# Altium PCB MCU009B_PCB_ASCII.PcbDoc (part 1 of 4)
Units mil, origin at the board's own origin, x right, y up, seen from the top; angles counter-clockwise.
Board outline 2657.23 x 2215.46 mil, 10 copper layers (Top Layer, Internal-Plane 2, Mid-Layer 3, Mid-Layer 4, Internal-Plane 5, Internal-Plane 6, Mid-Layer 7, Mid-Layer 8, Internal-Plane 9, Bottom Layer), stack 60.8 mil thick; 232 components, 196 nets, 851 pads, 493 vias.
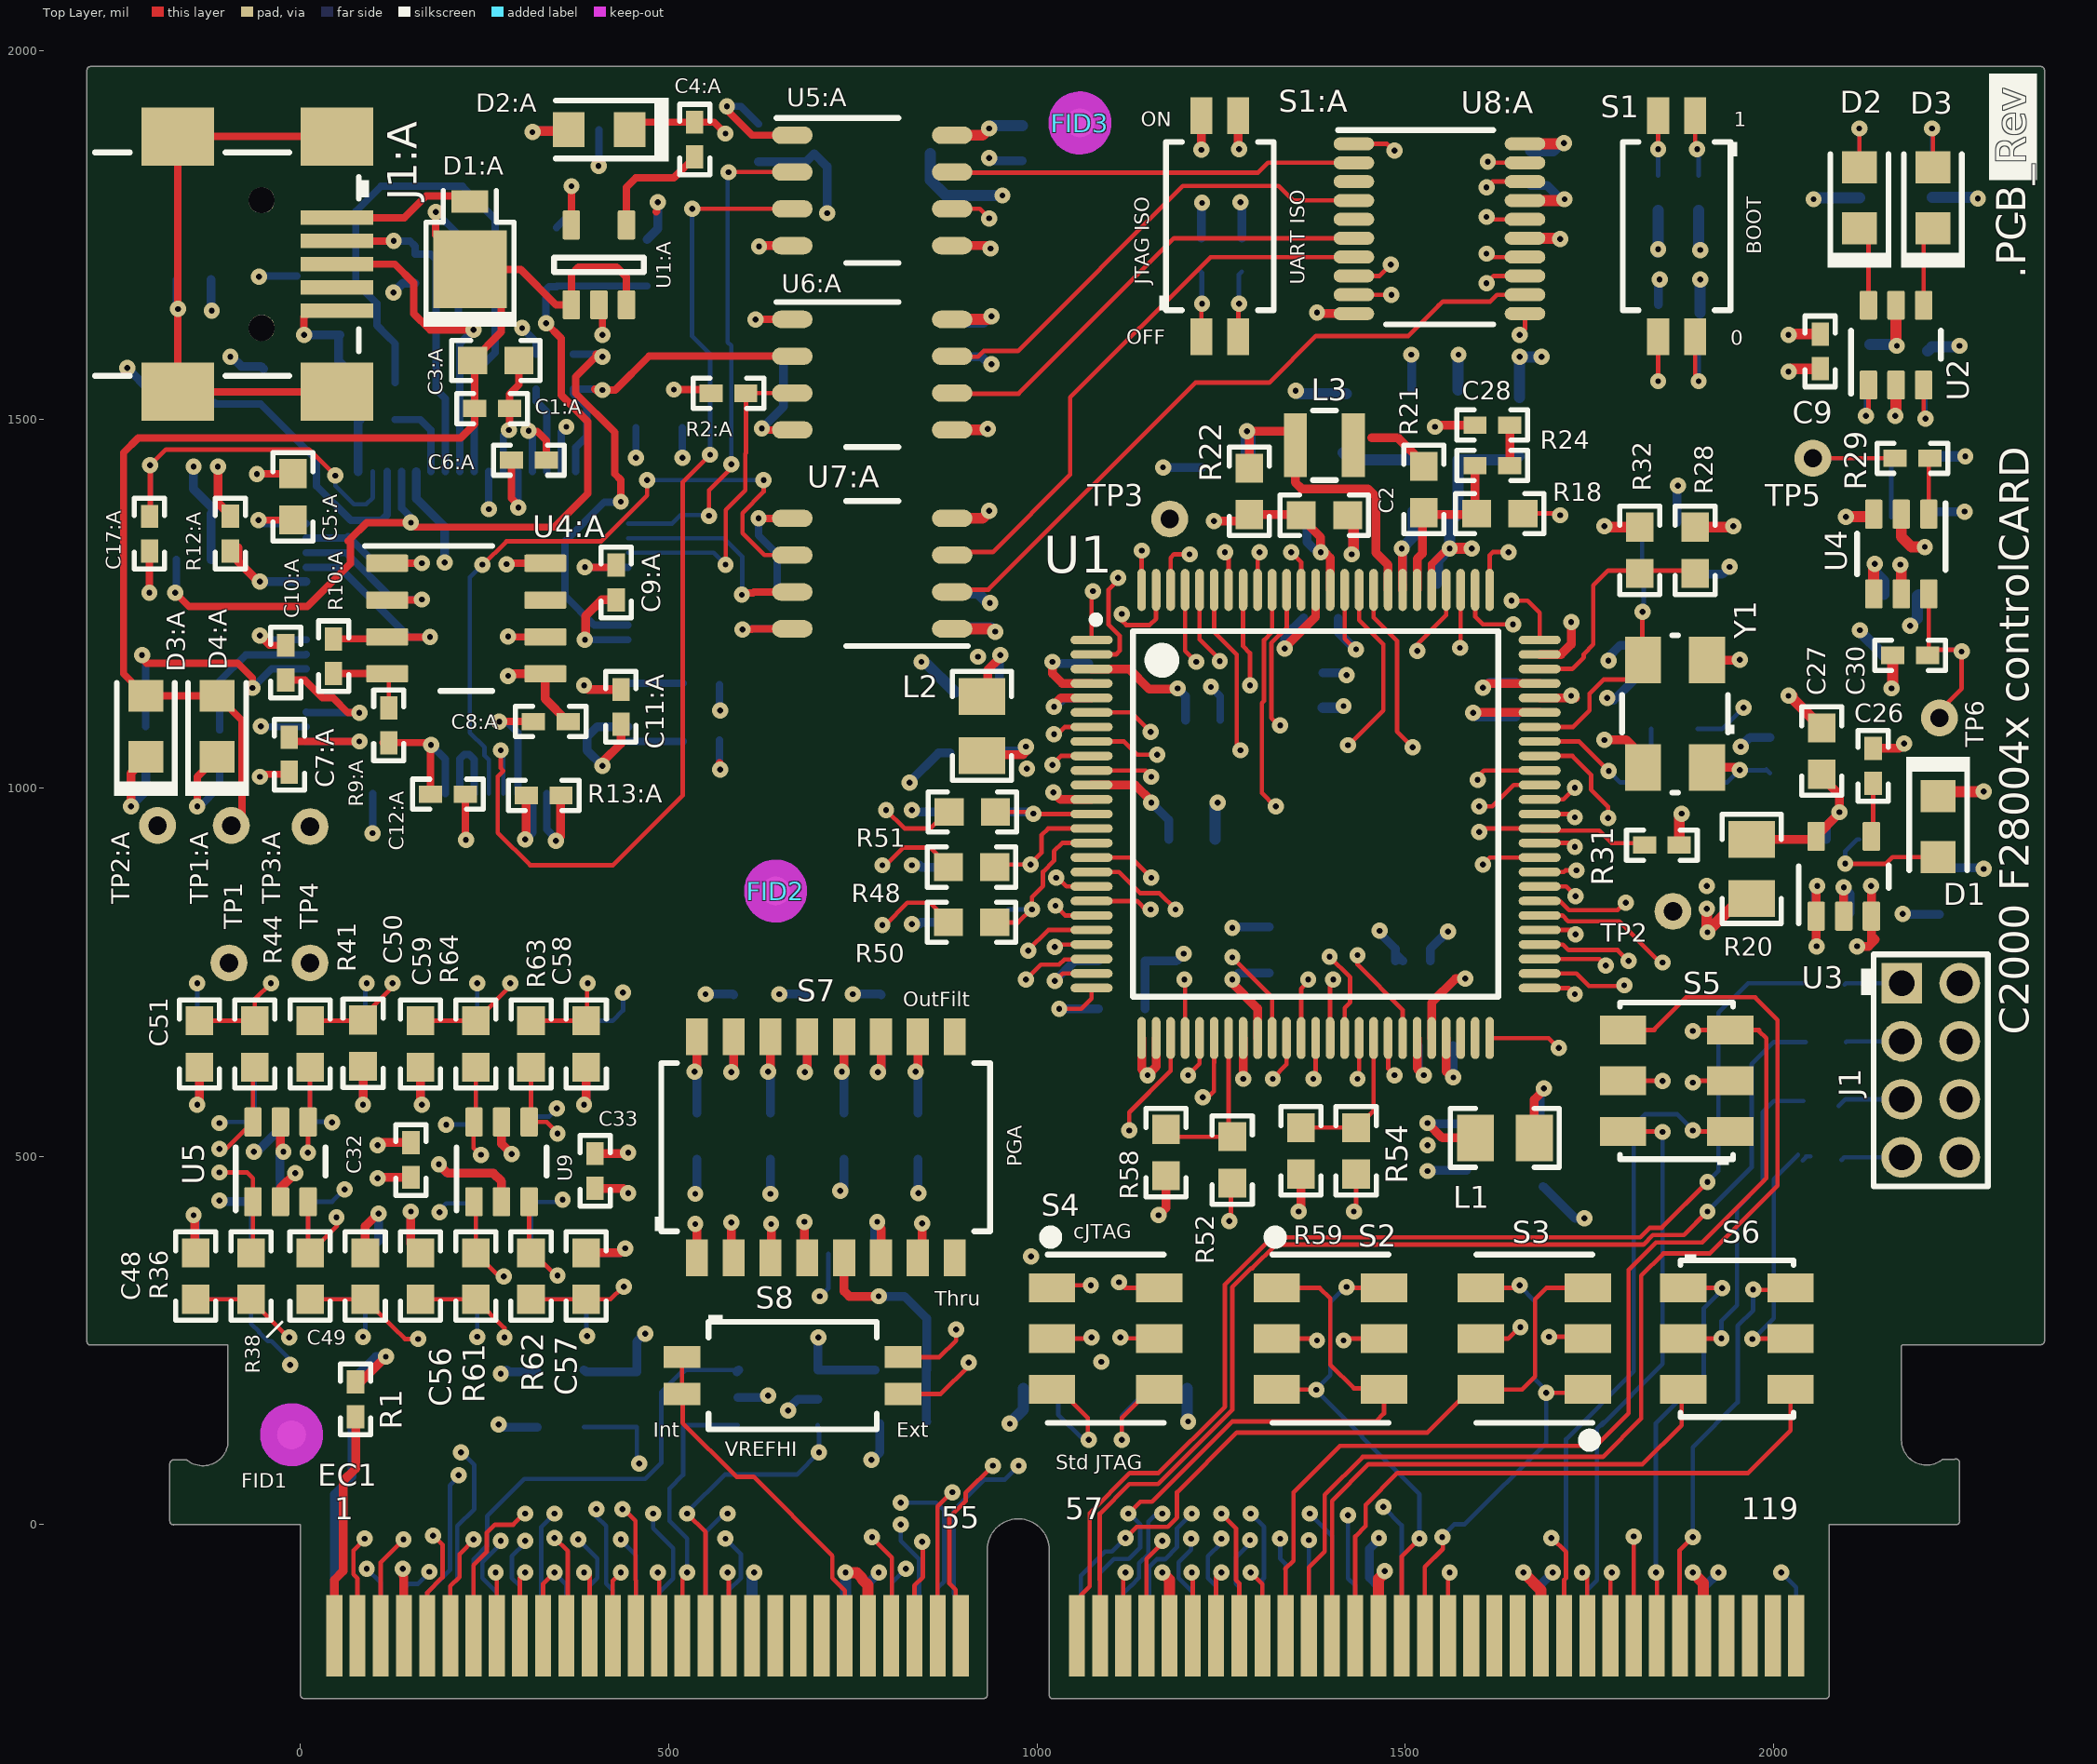
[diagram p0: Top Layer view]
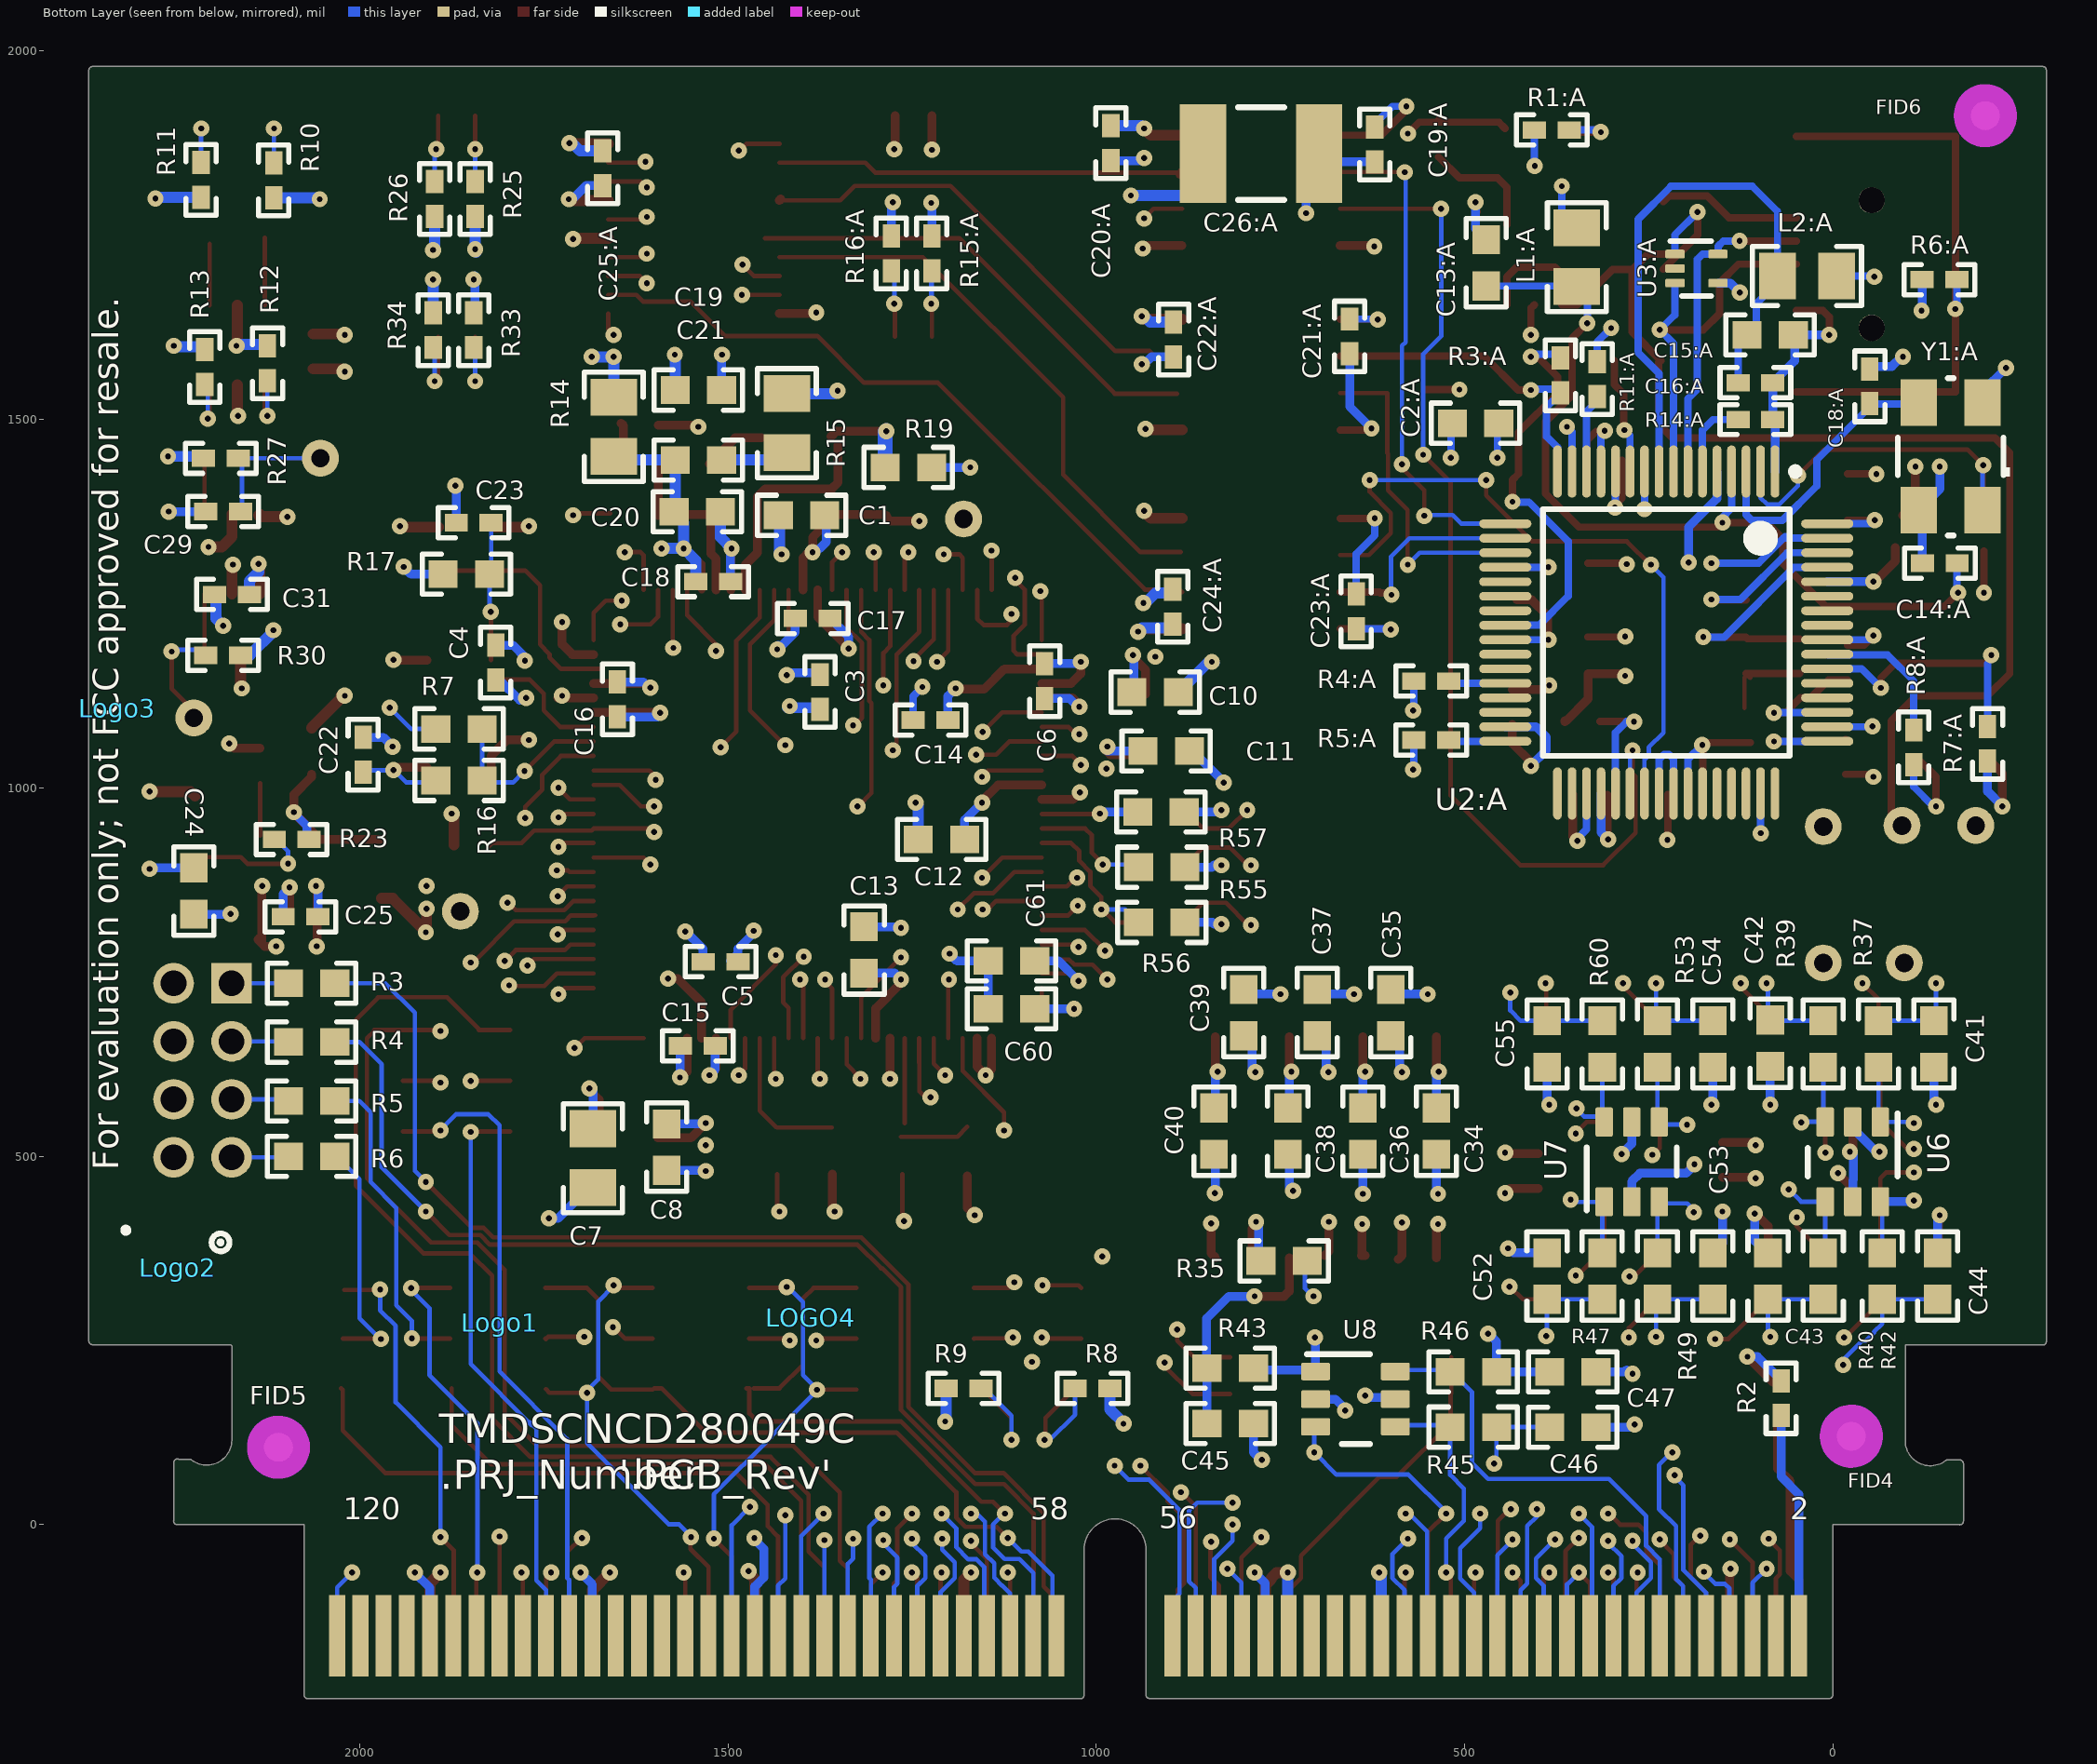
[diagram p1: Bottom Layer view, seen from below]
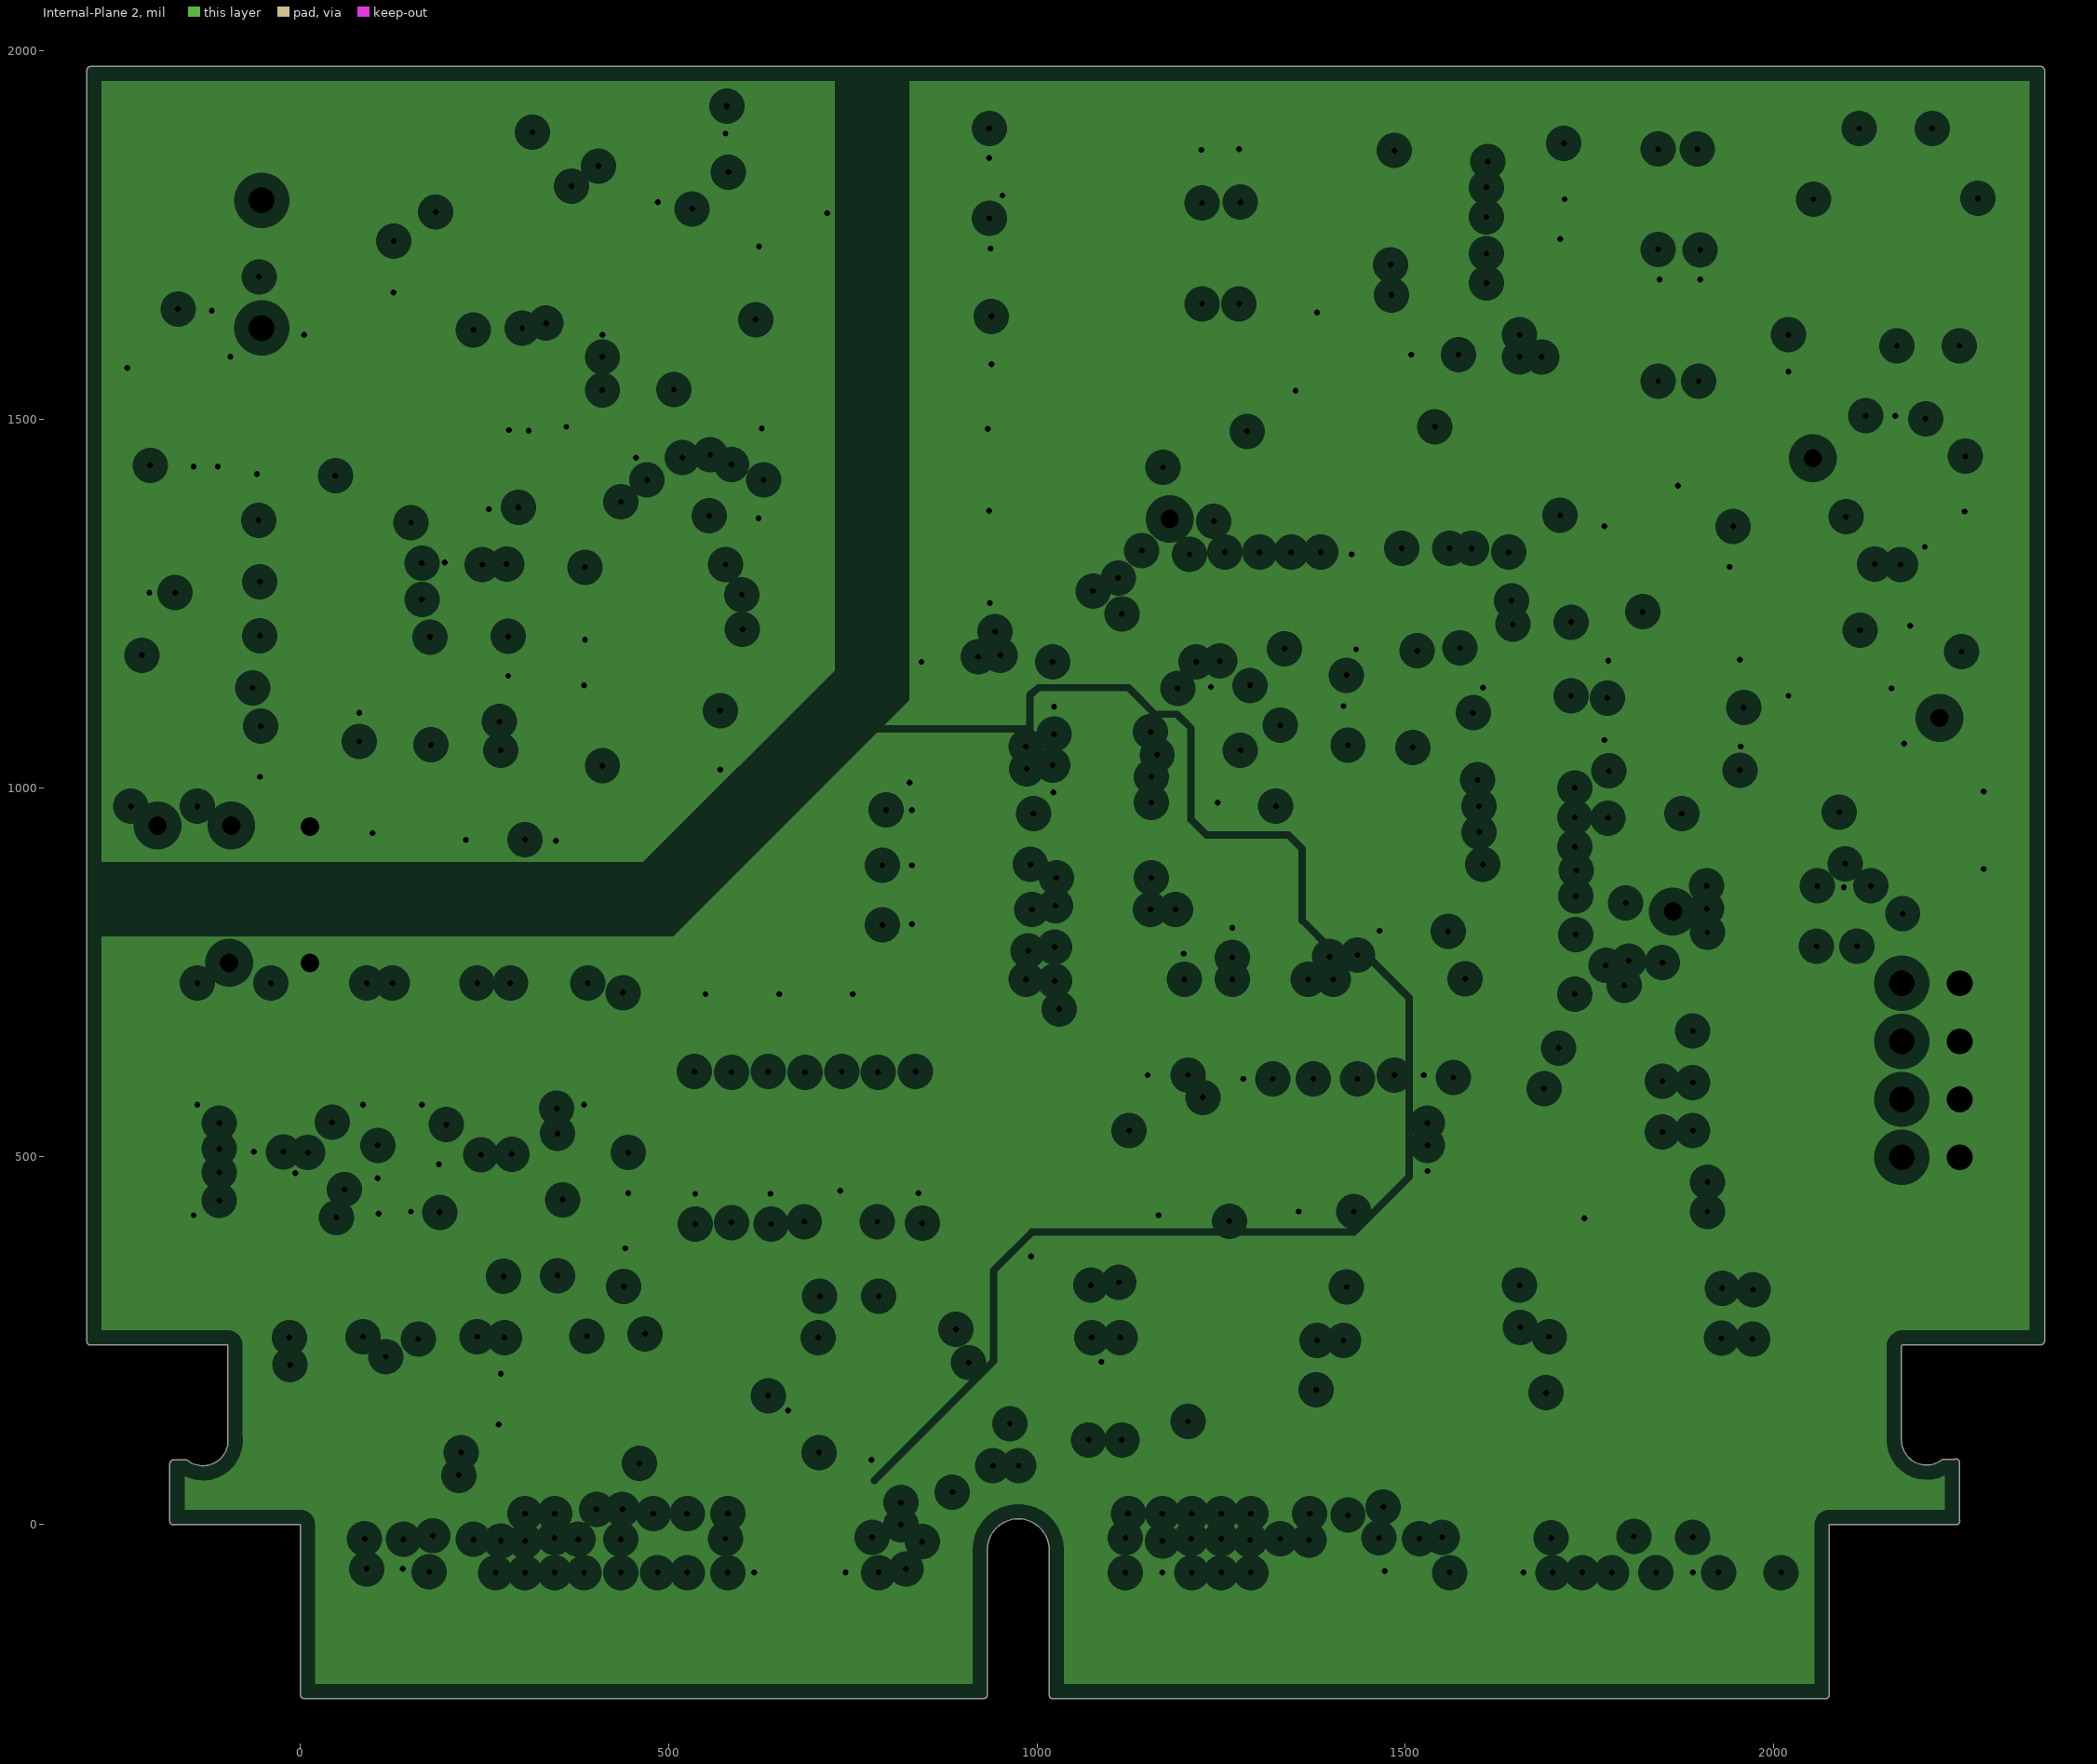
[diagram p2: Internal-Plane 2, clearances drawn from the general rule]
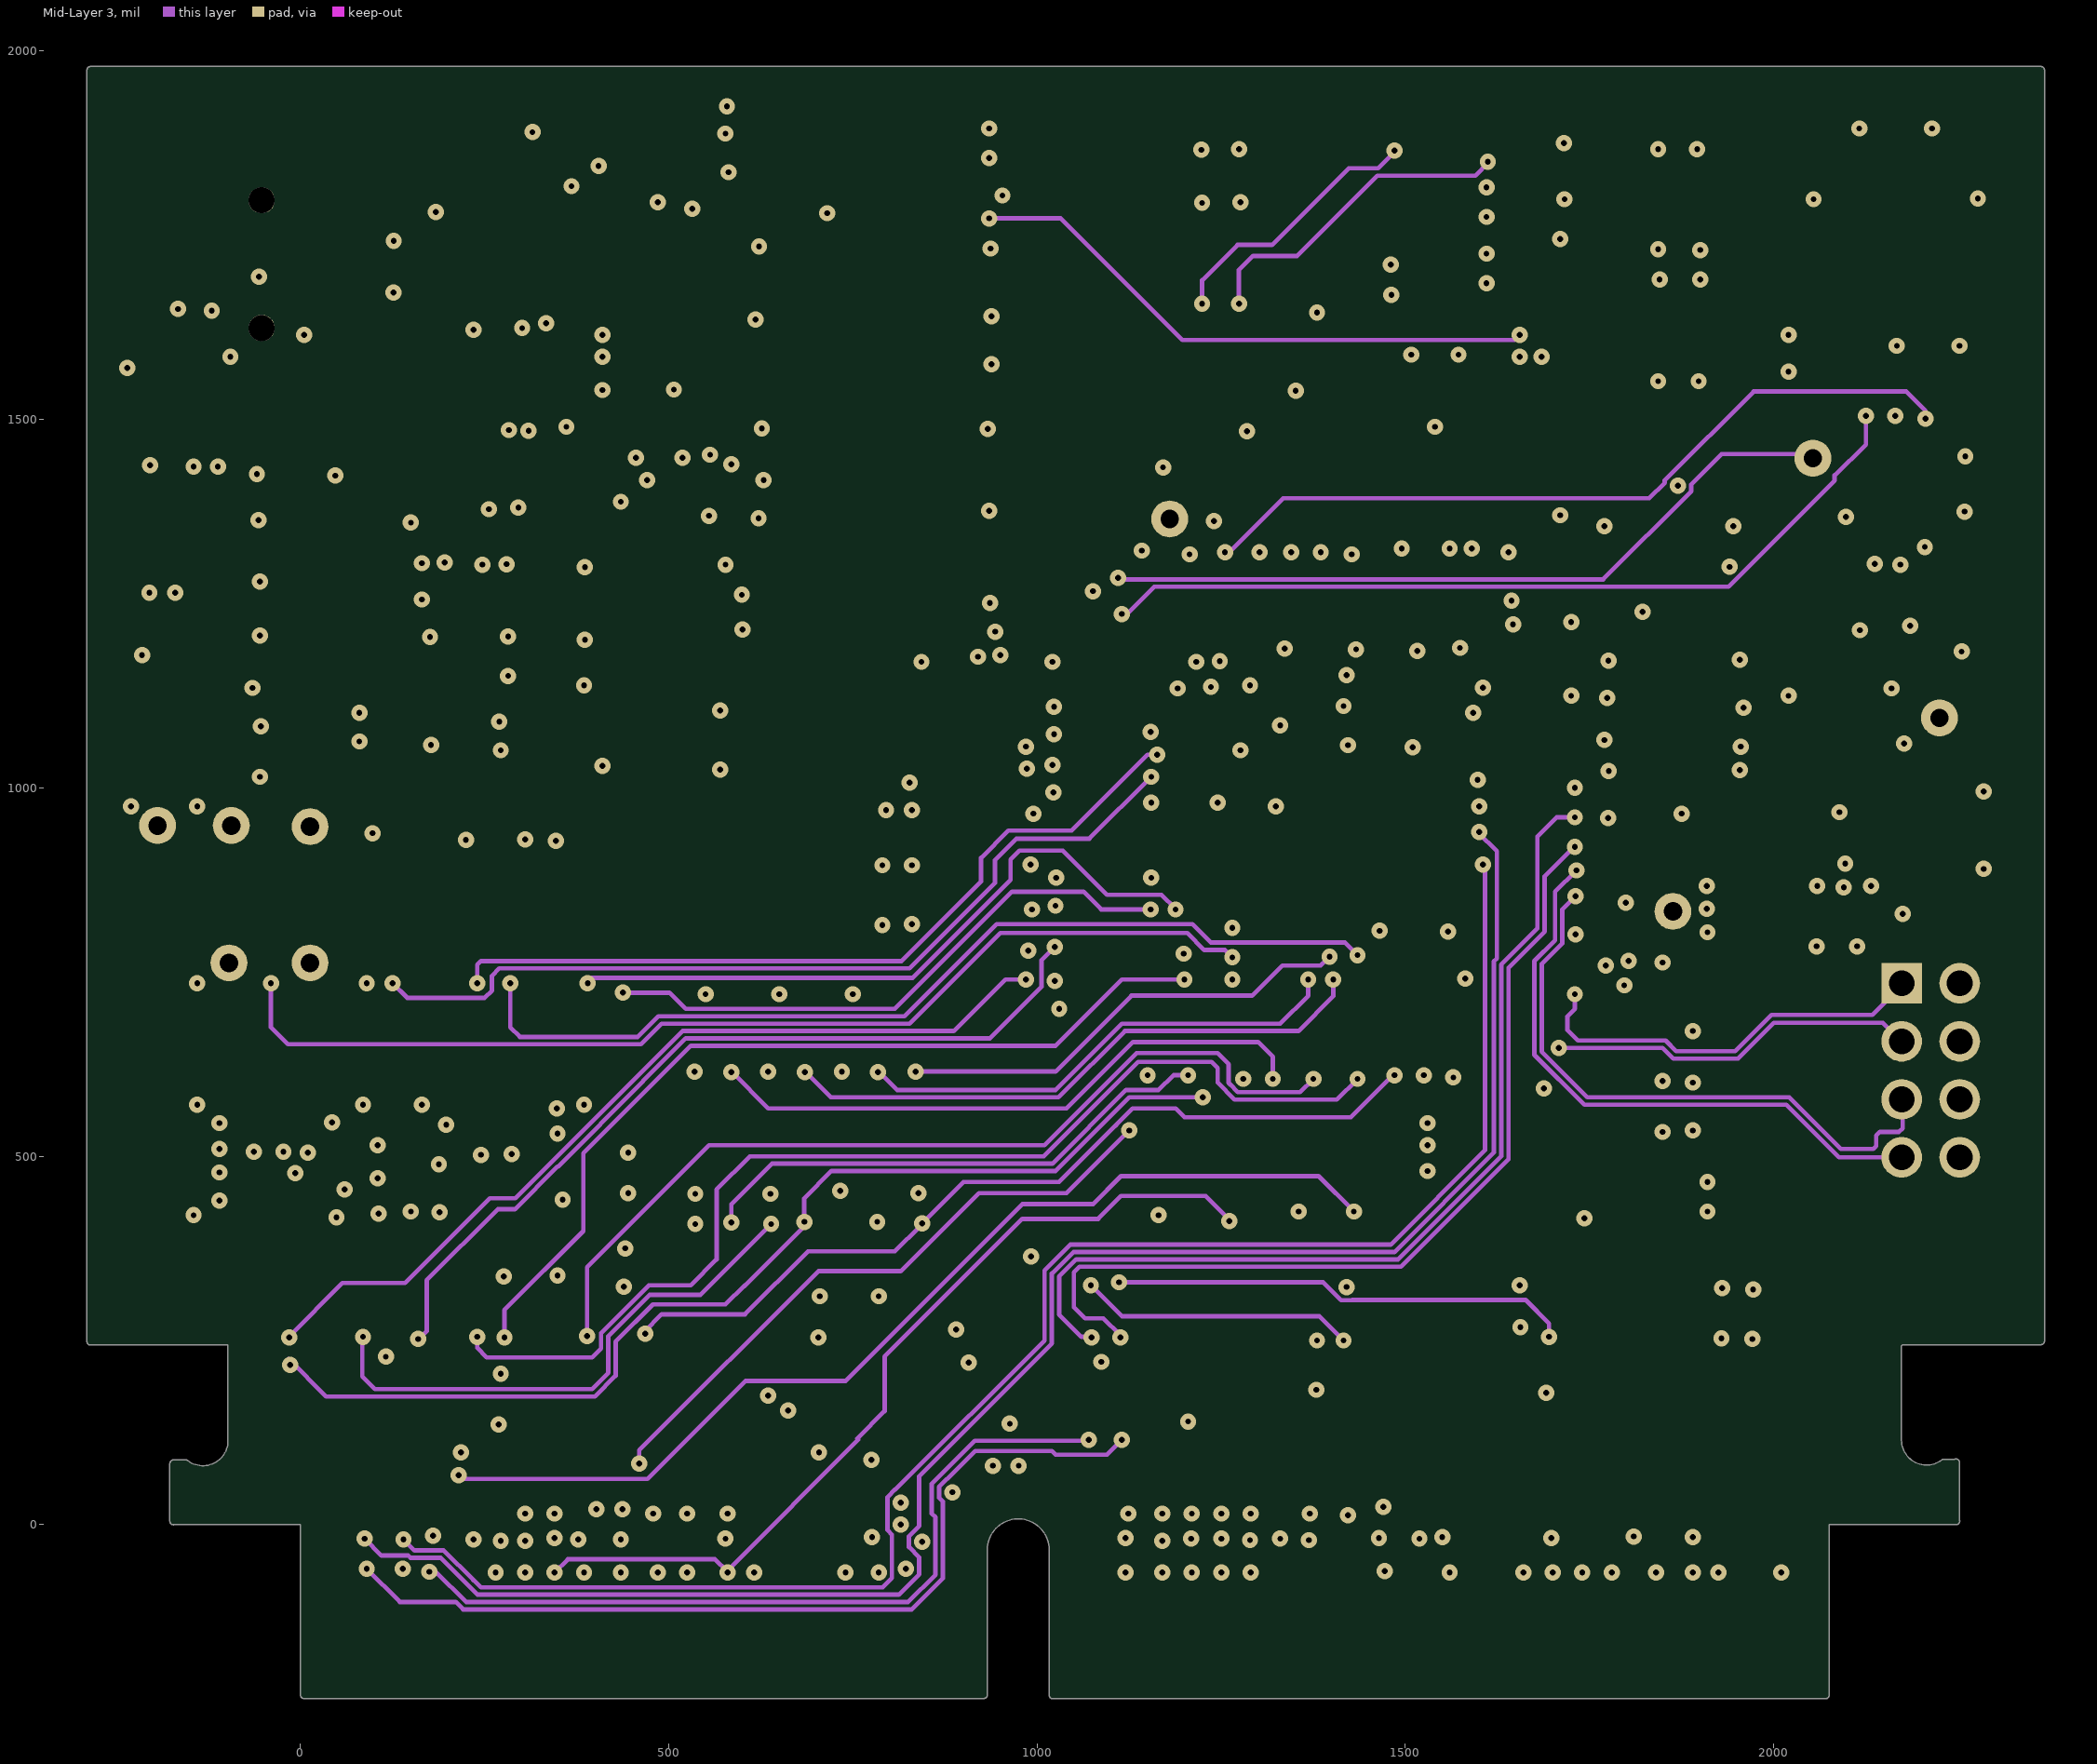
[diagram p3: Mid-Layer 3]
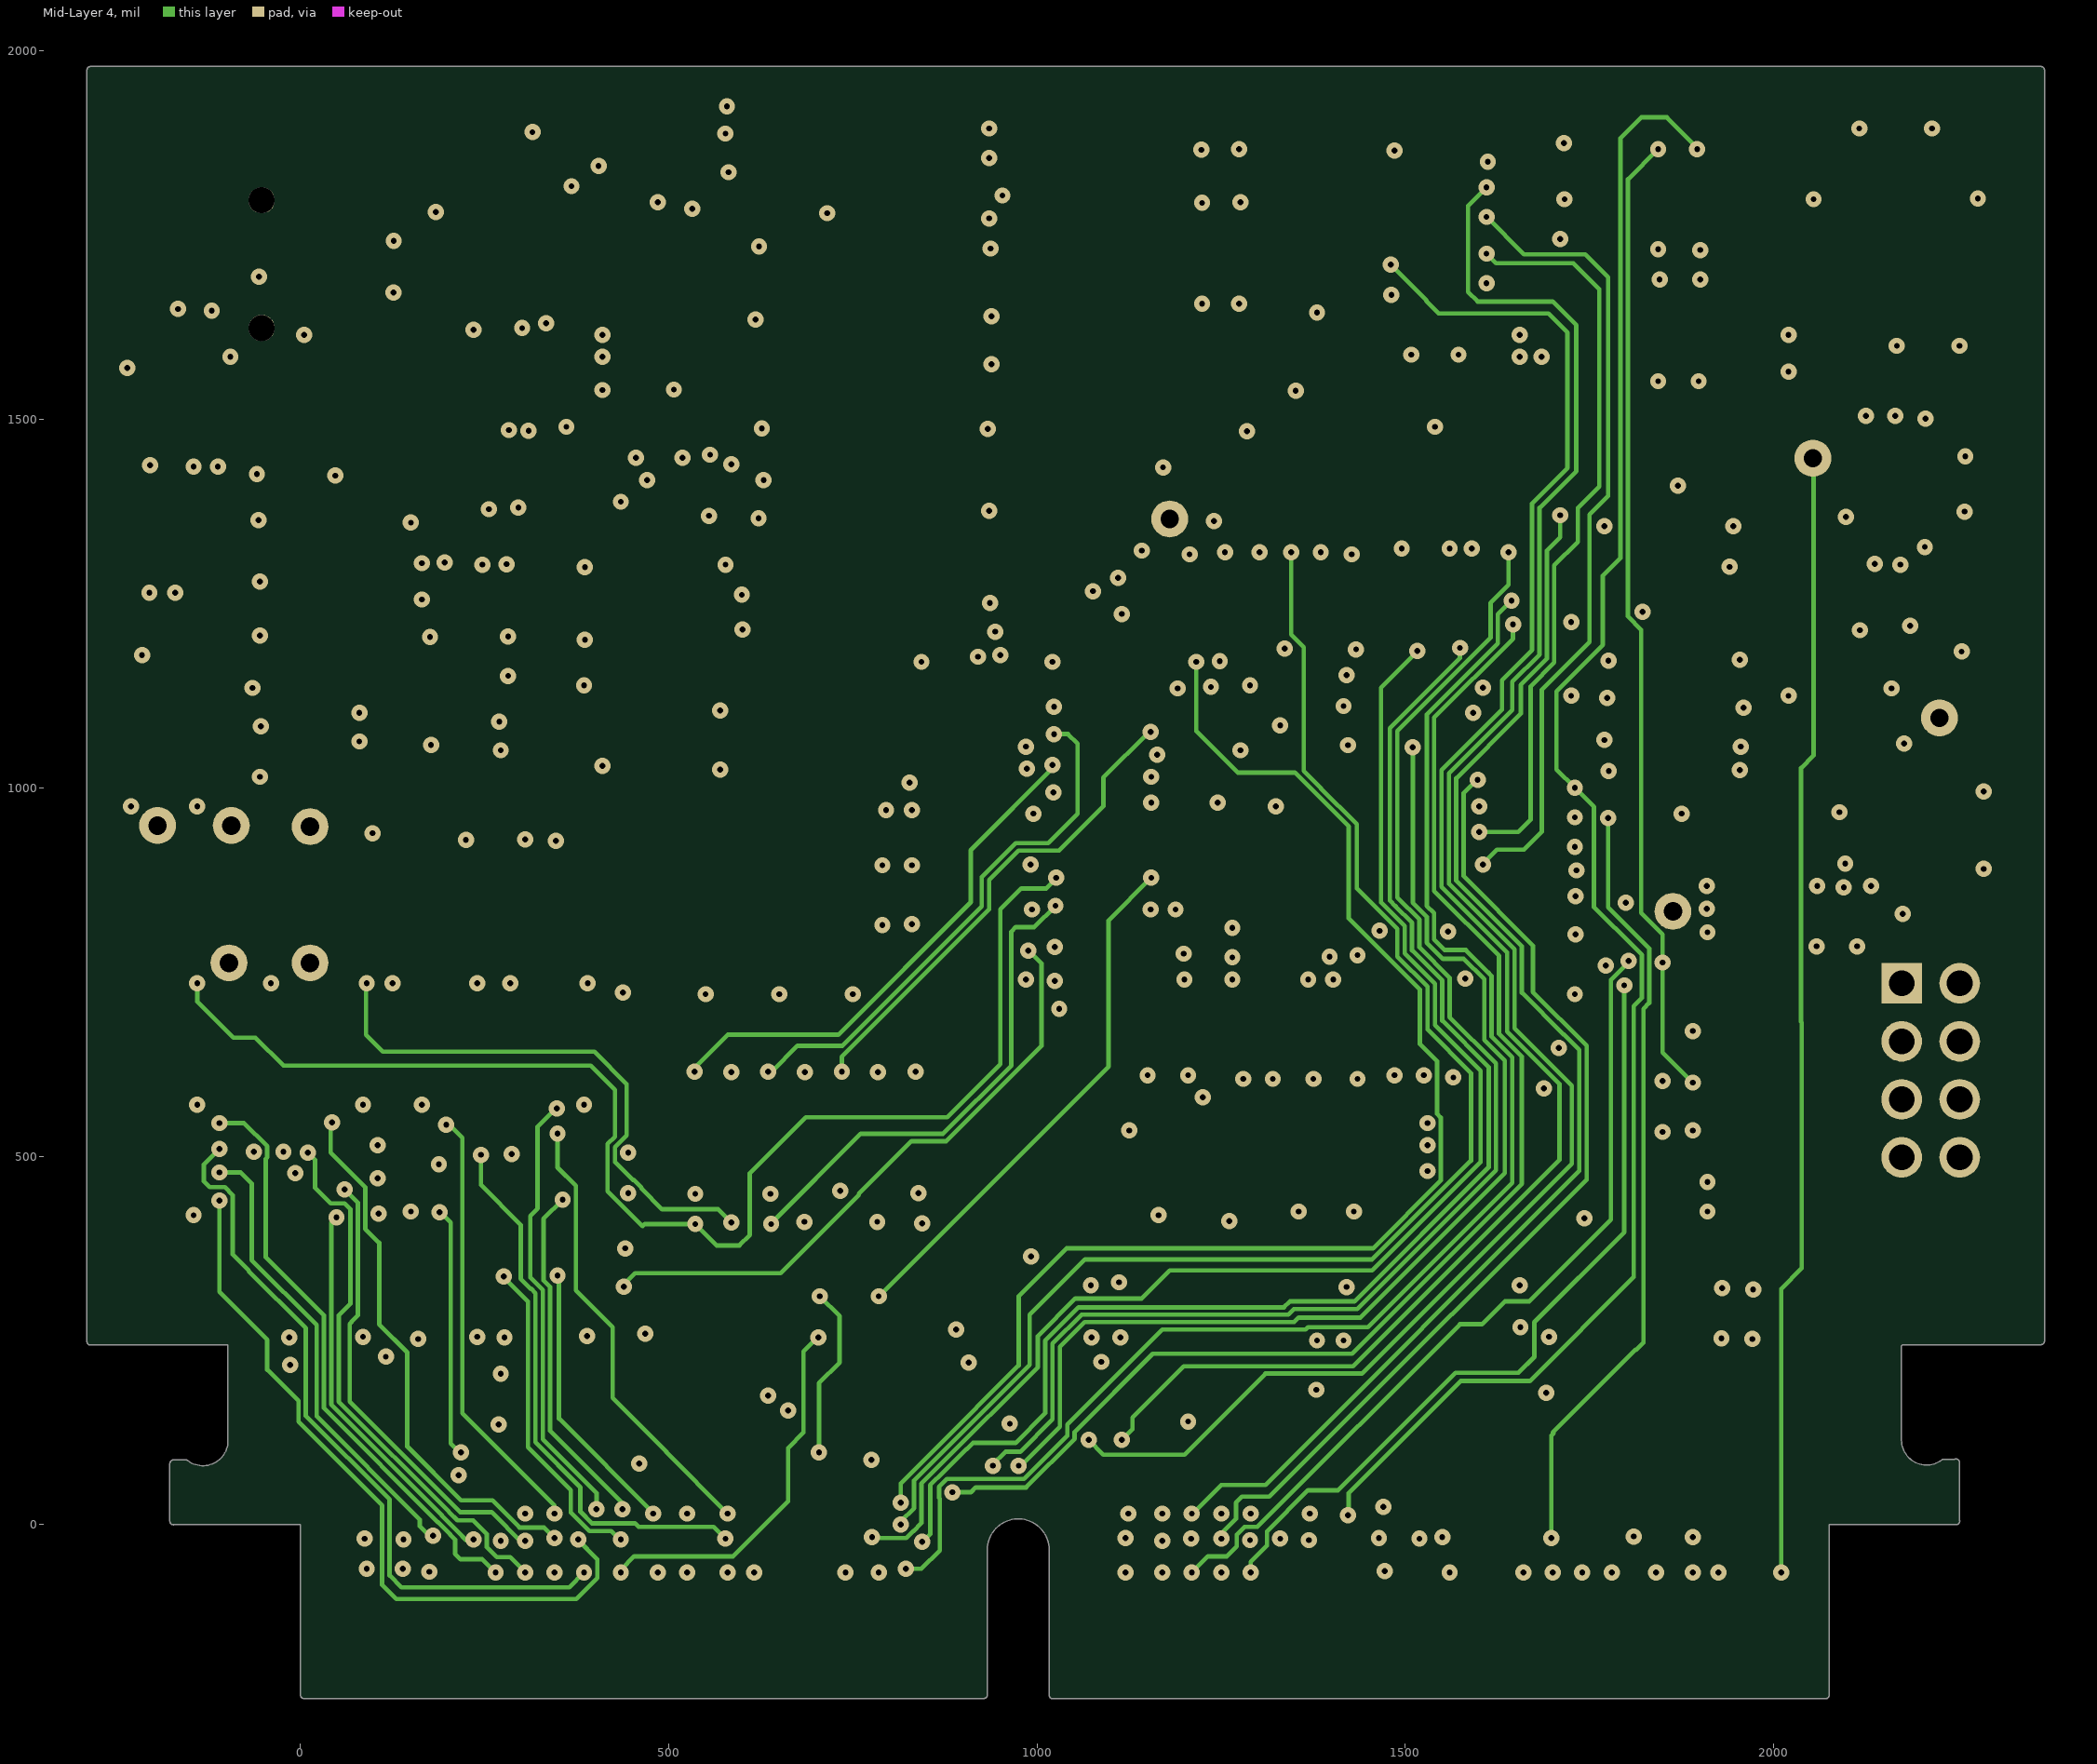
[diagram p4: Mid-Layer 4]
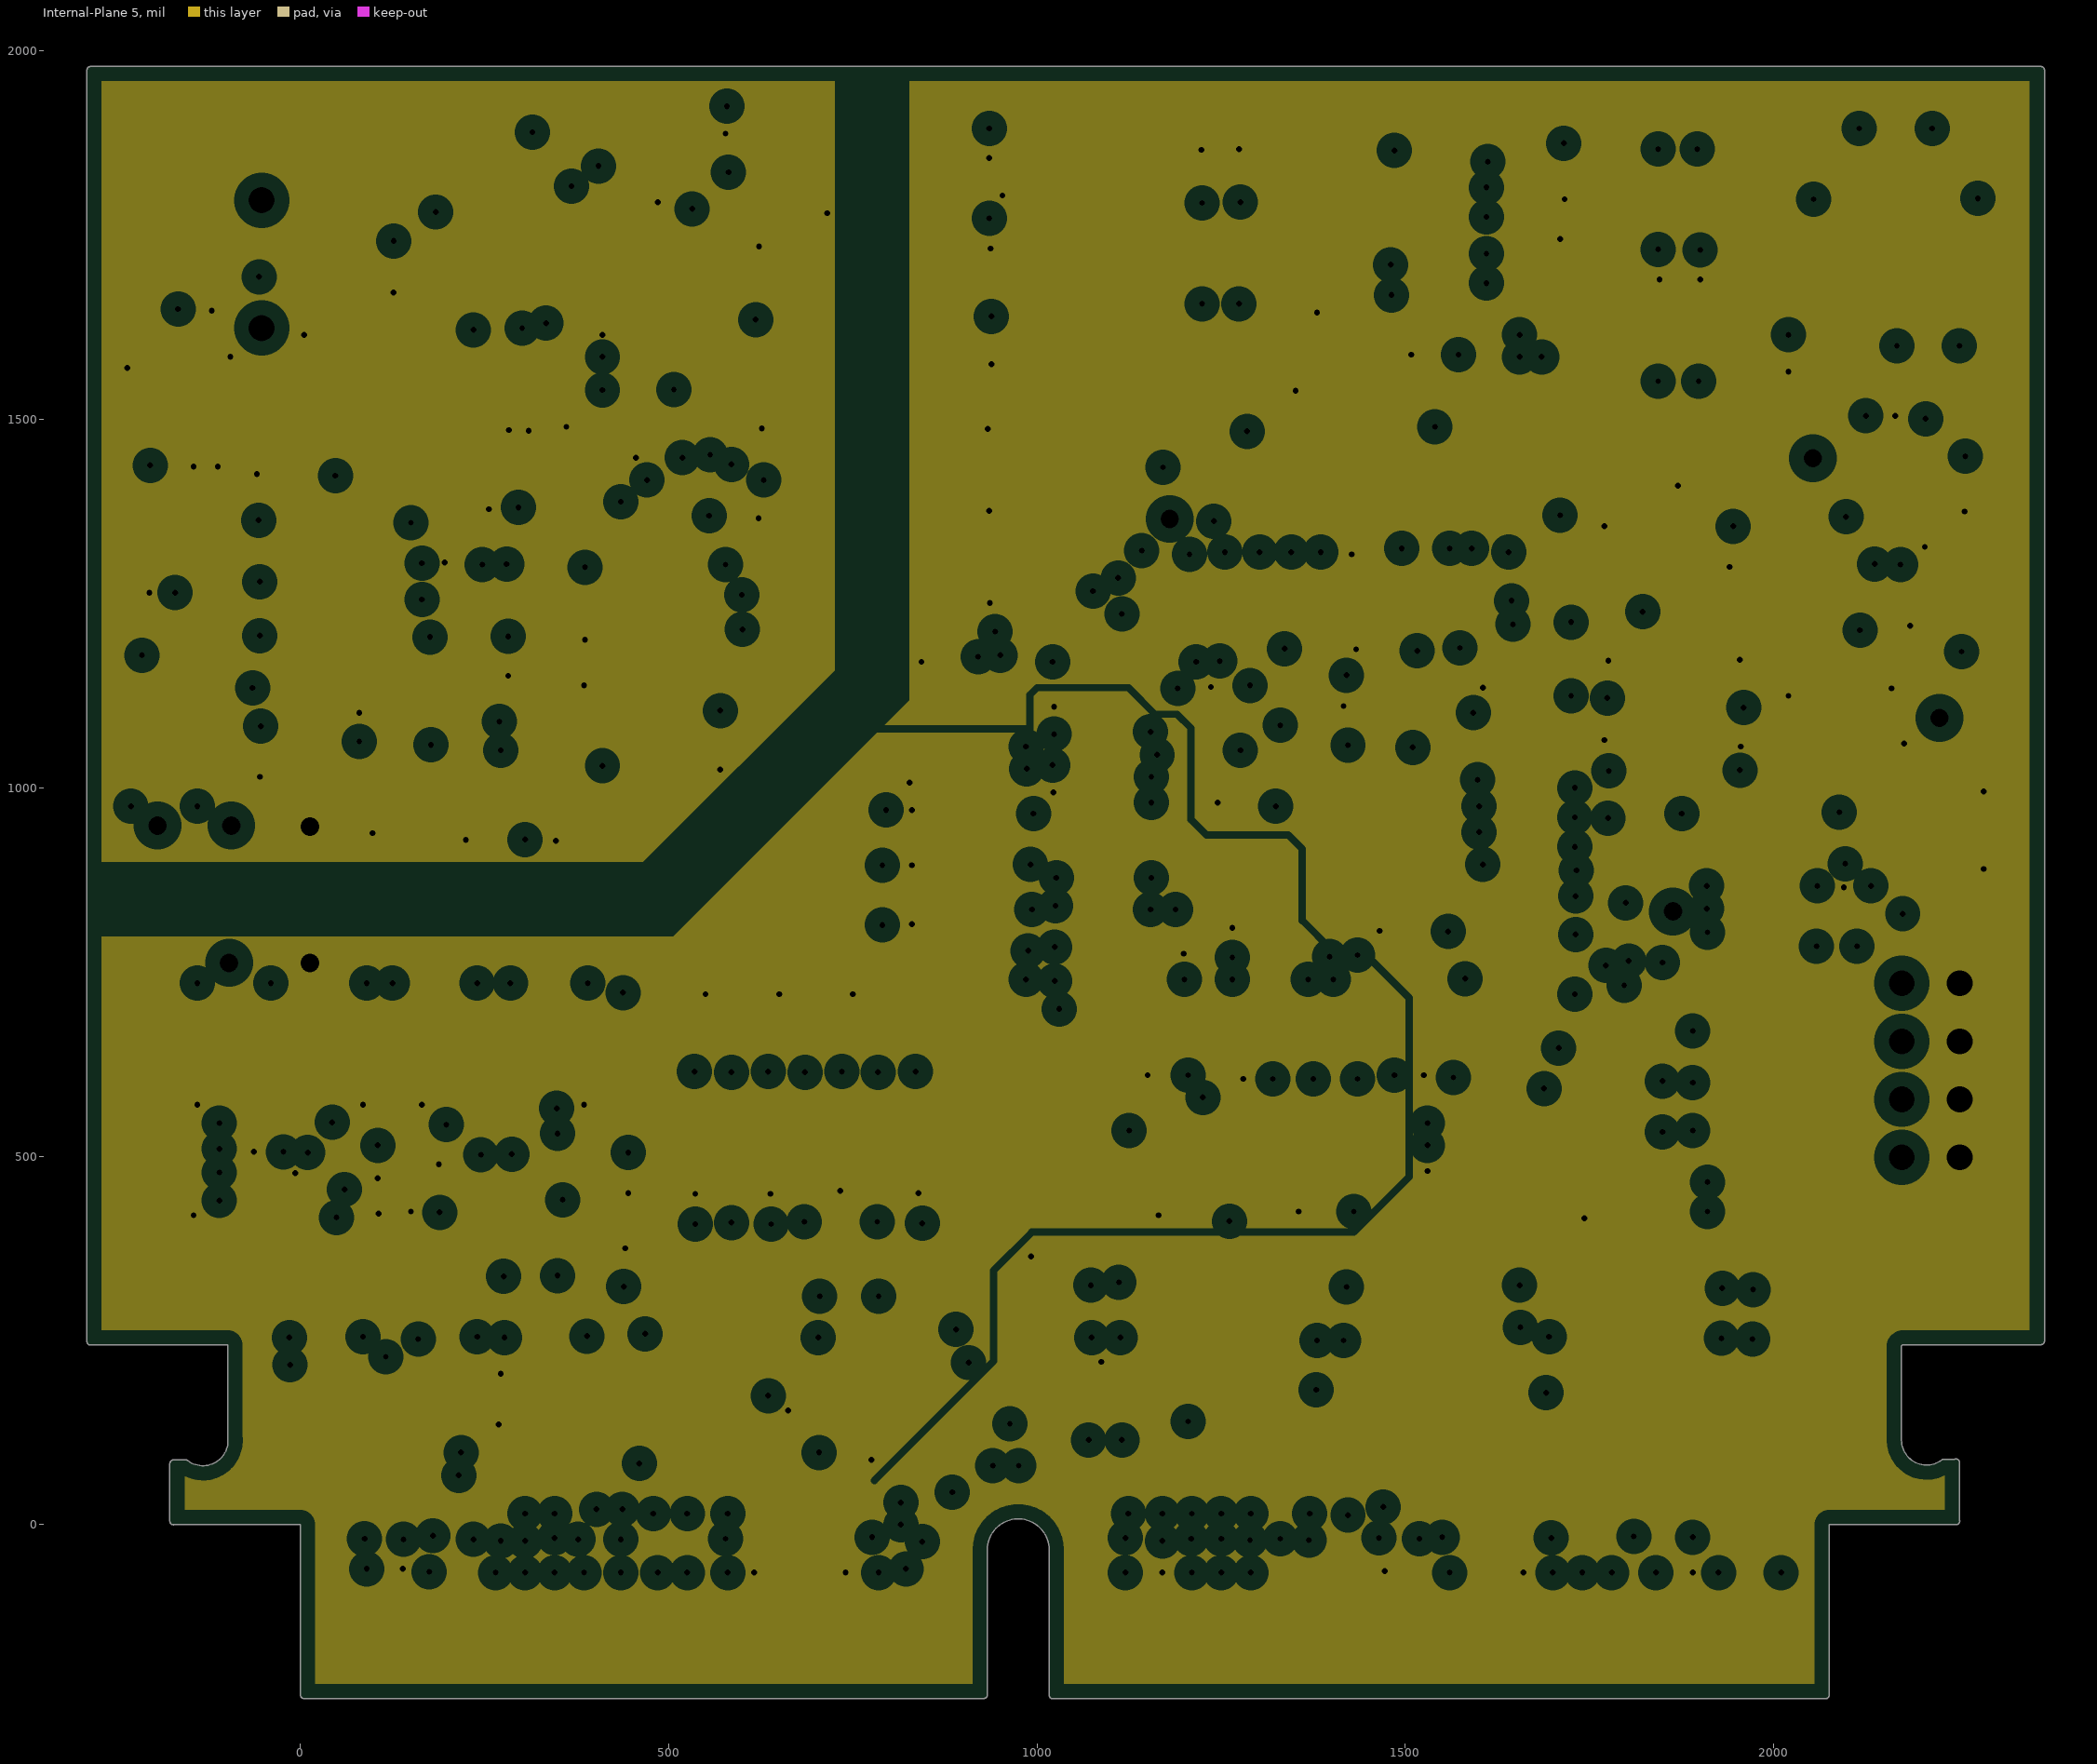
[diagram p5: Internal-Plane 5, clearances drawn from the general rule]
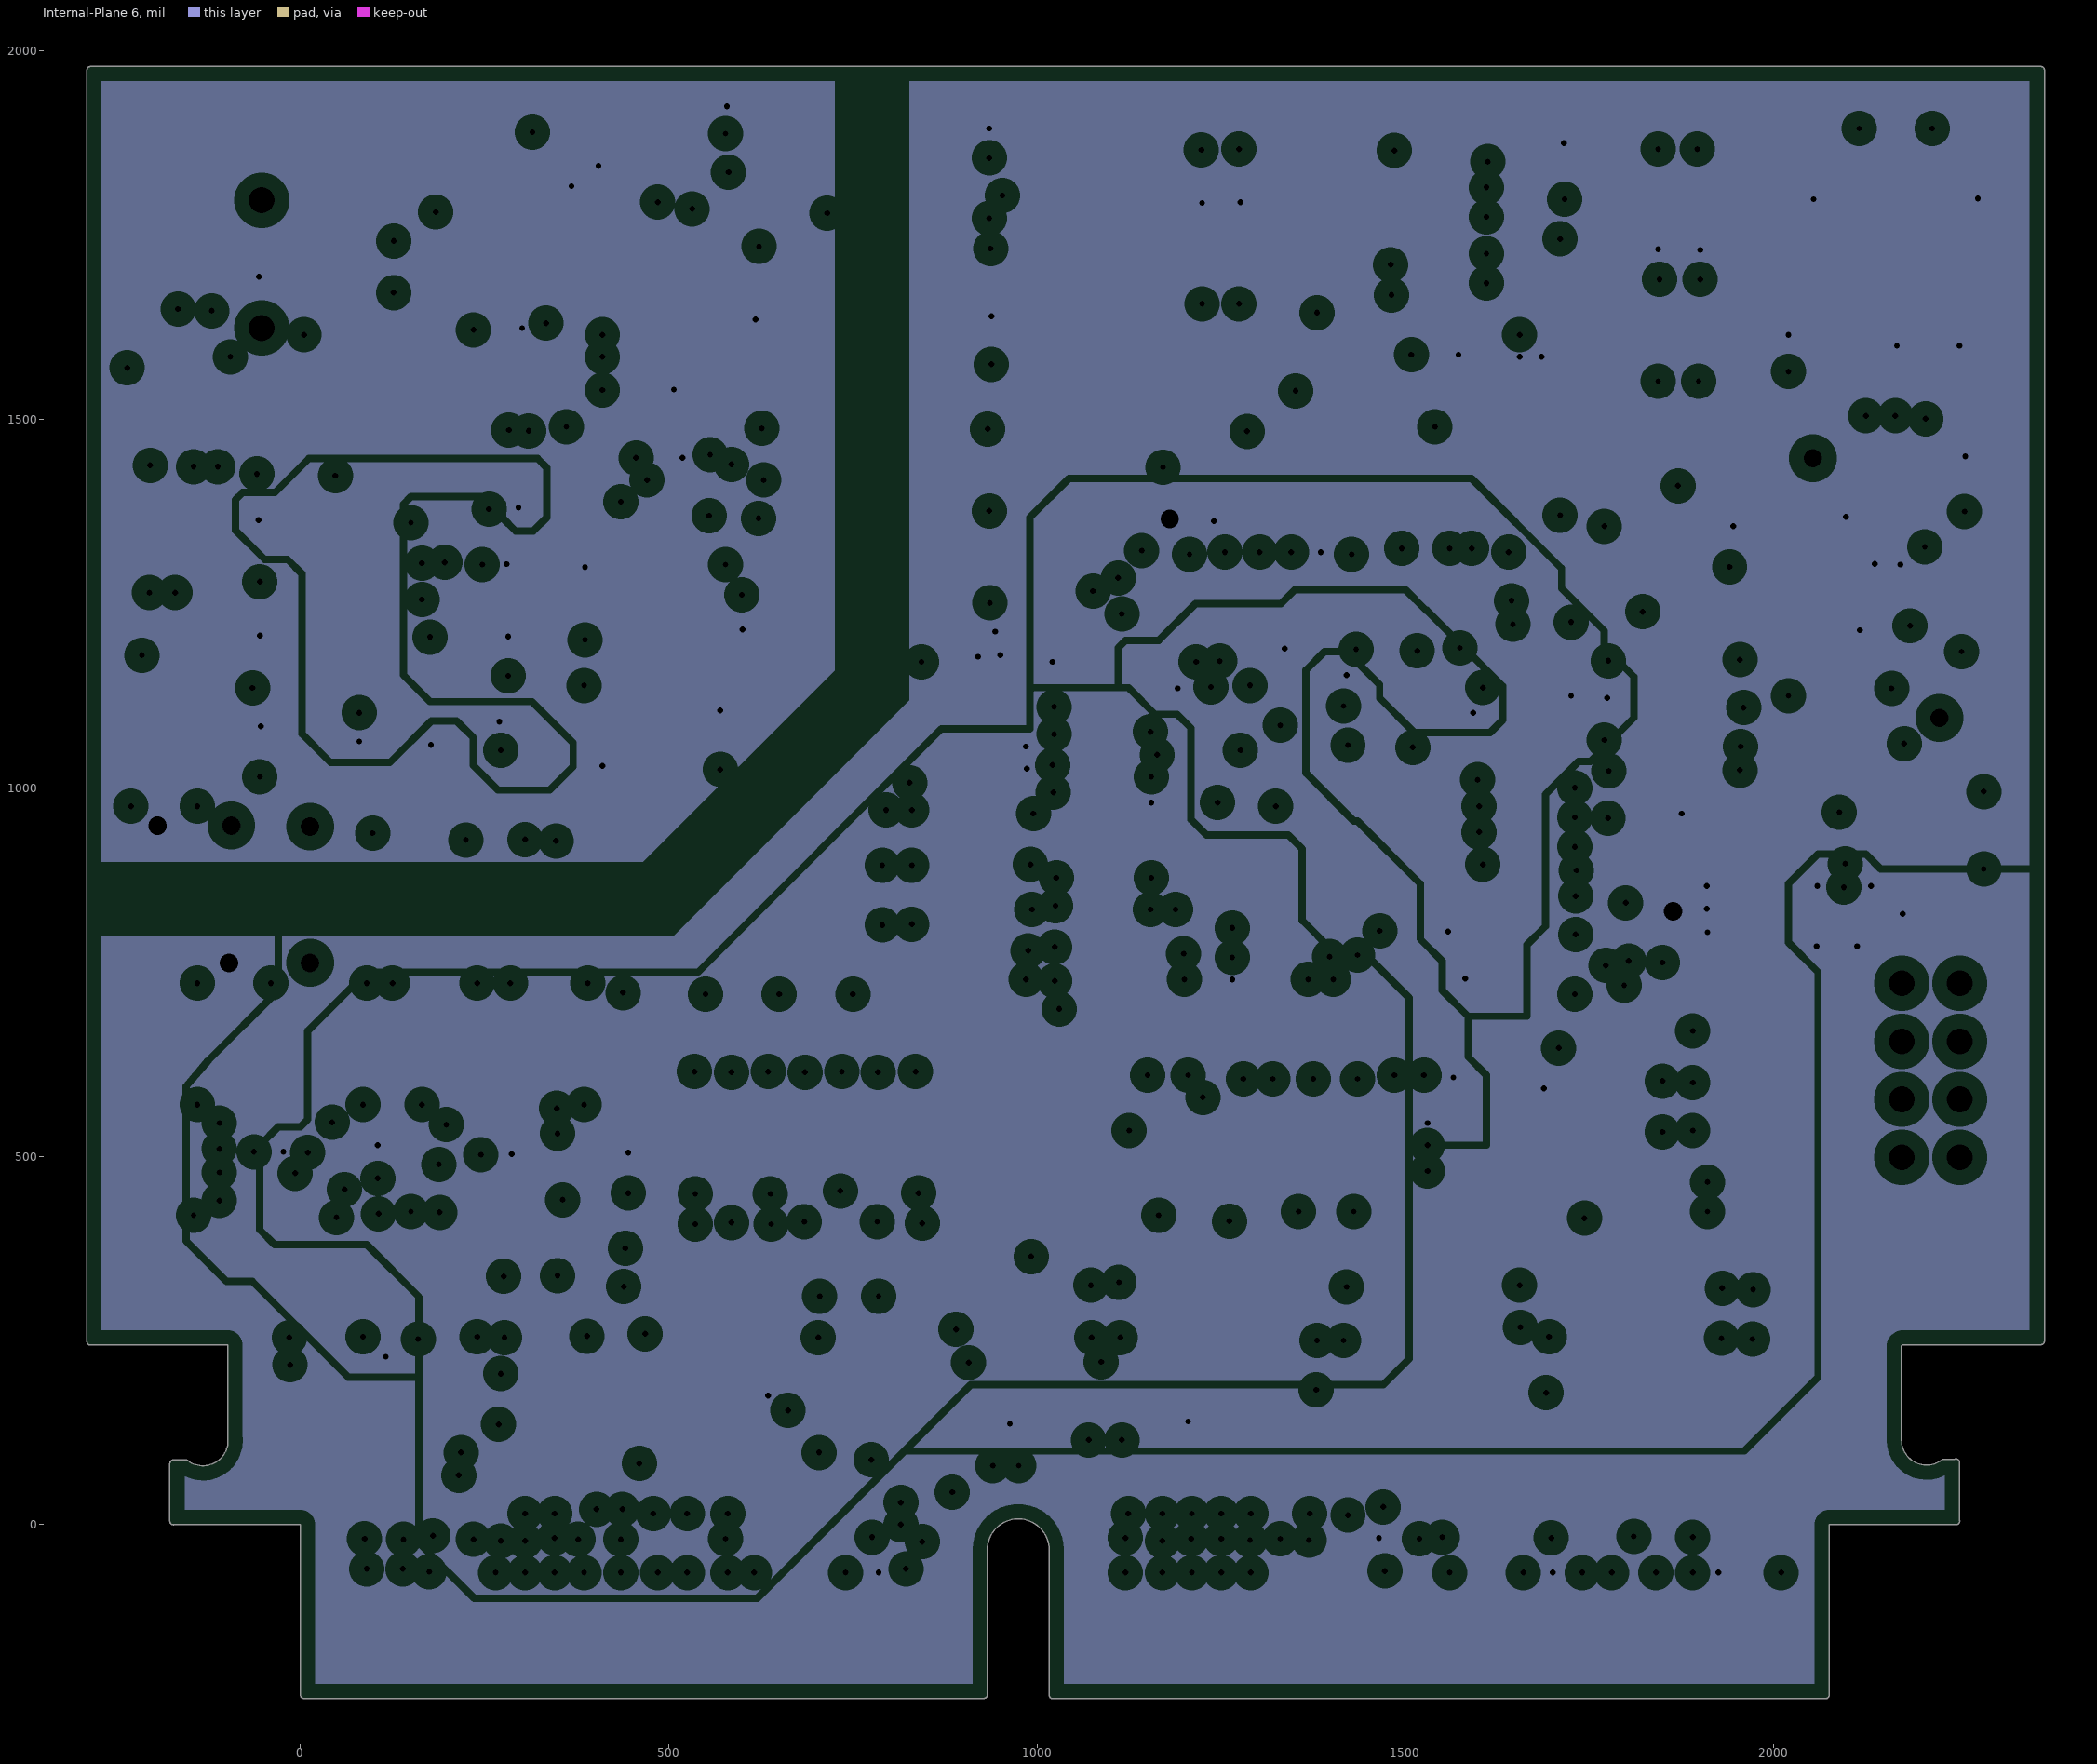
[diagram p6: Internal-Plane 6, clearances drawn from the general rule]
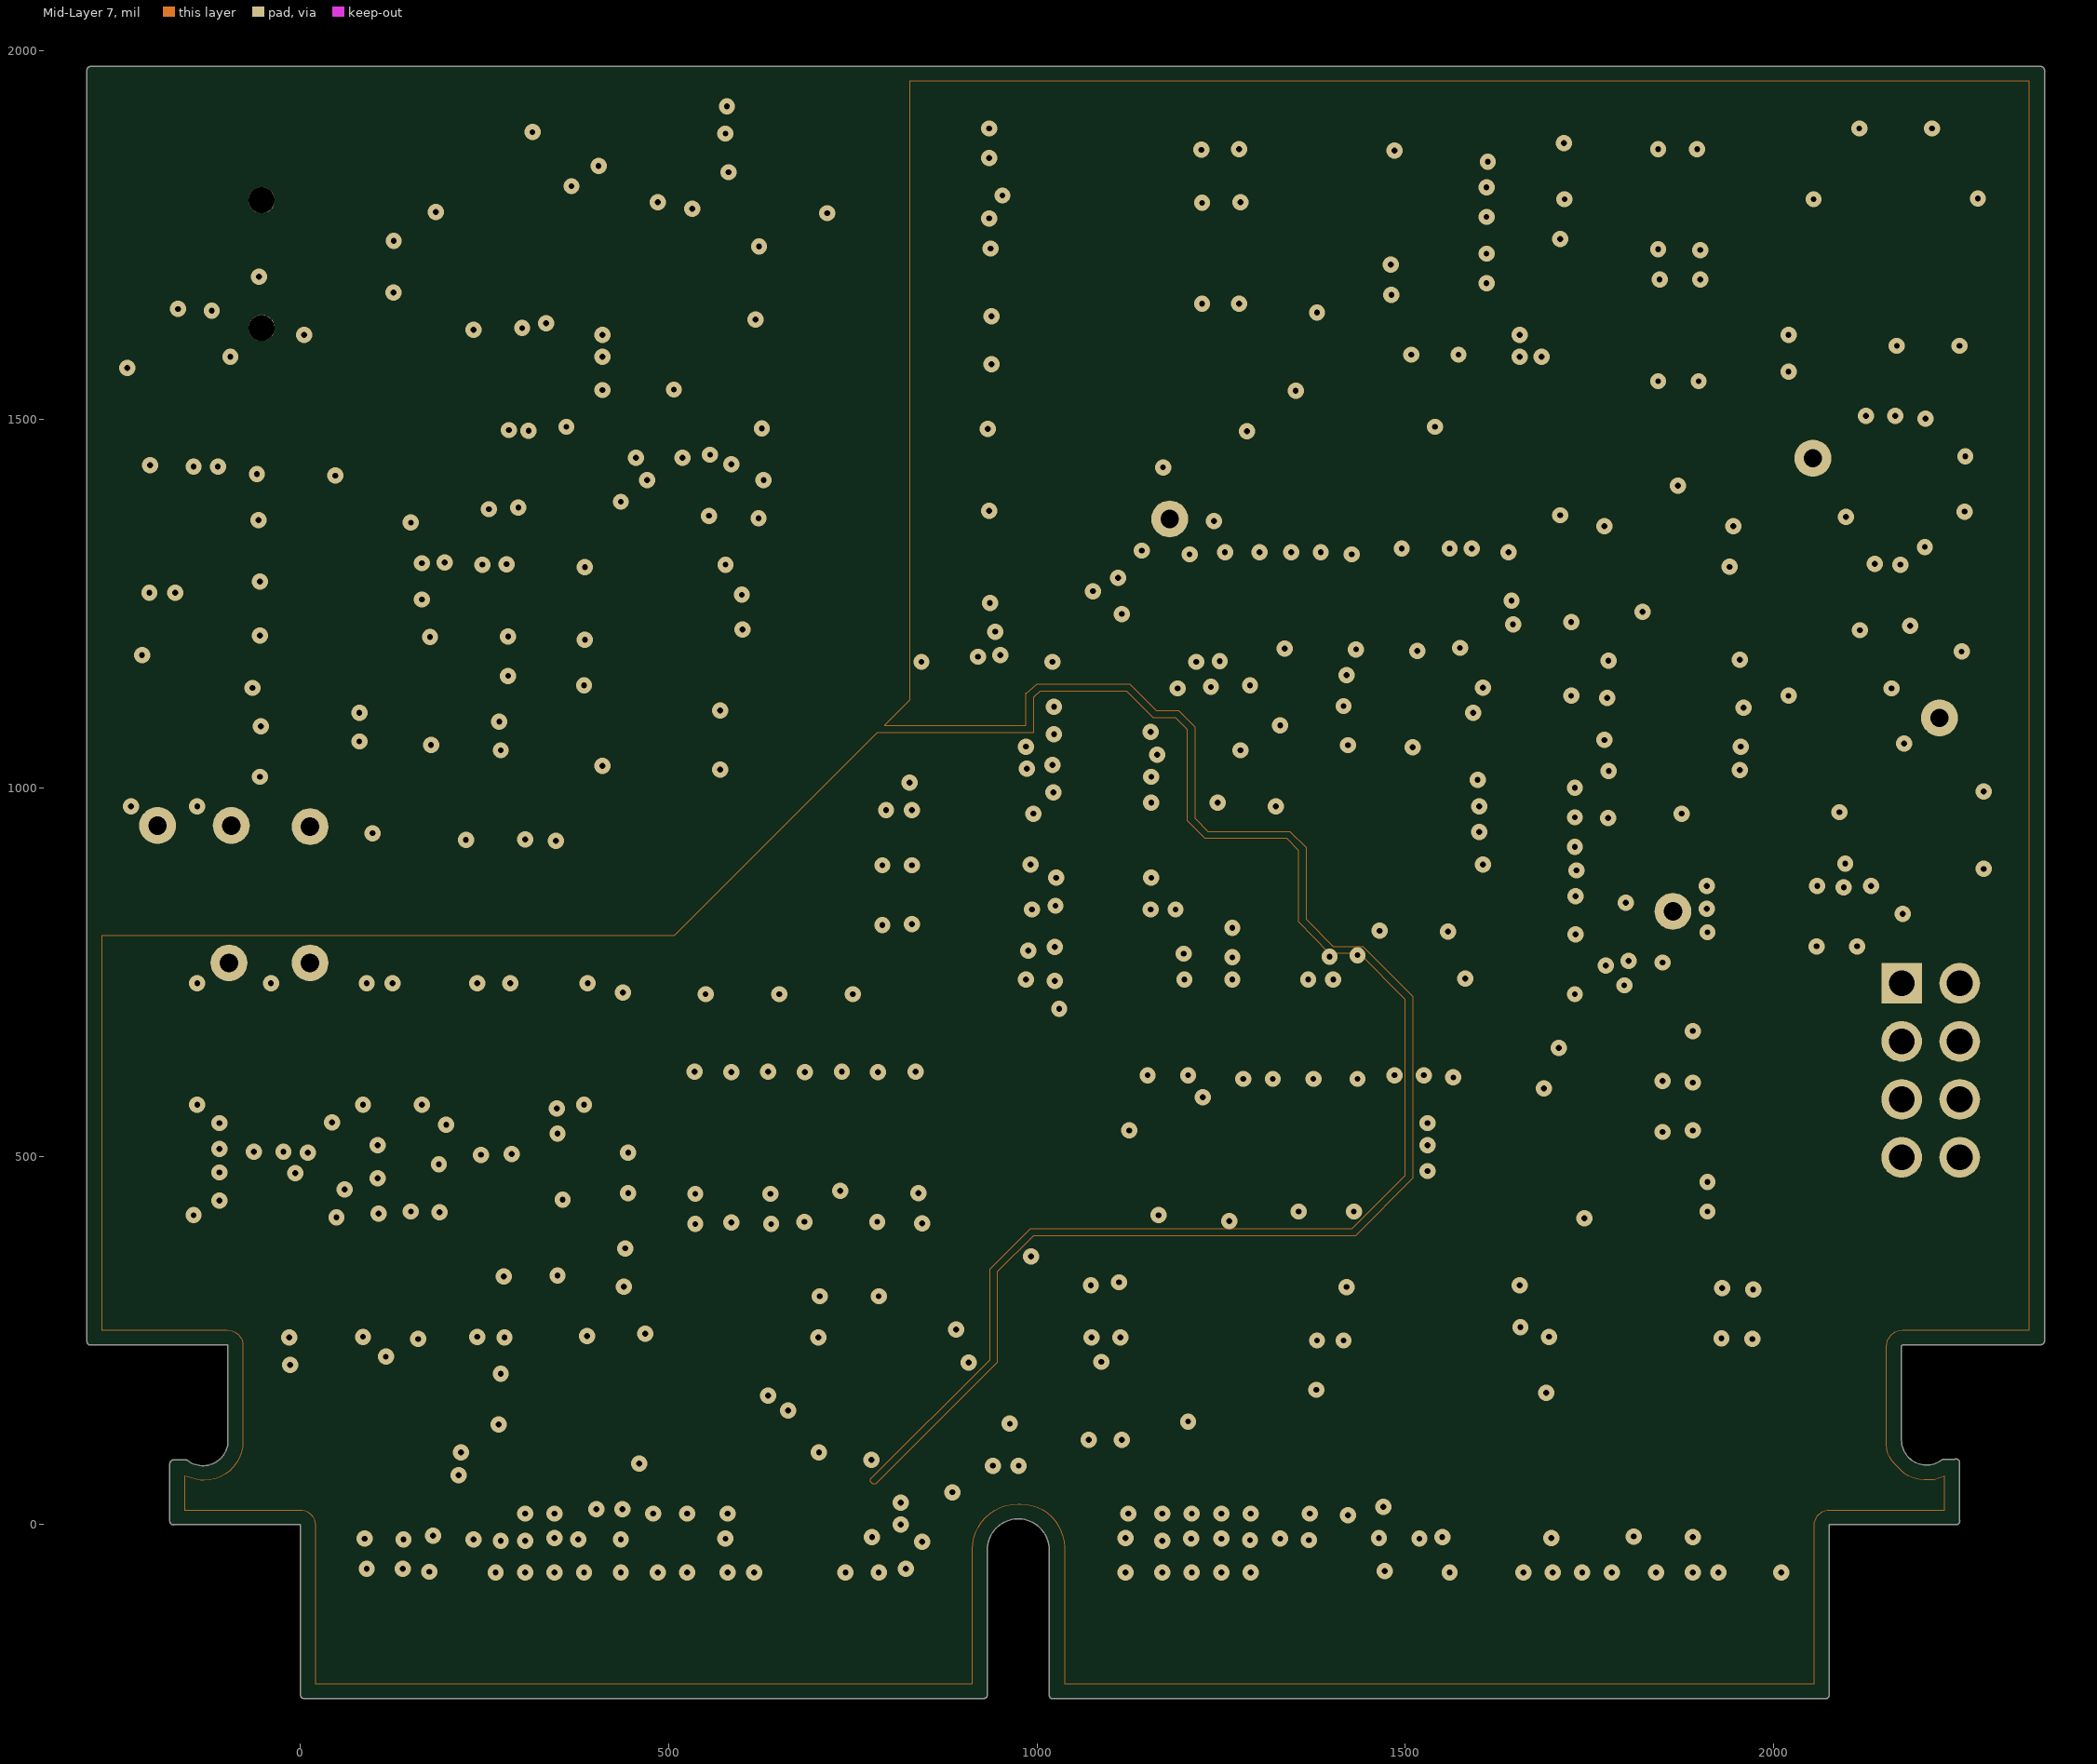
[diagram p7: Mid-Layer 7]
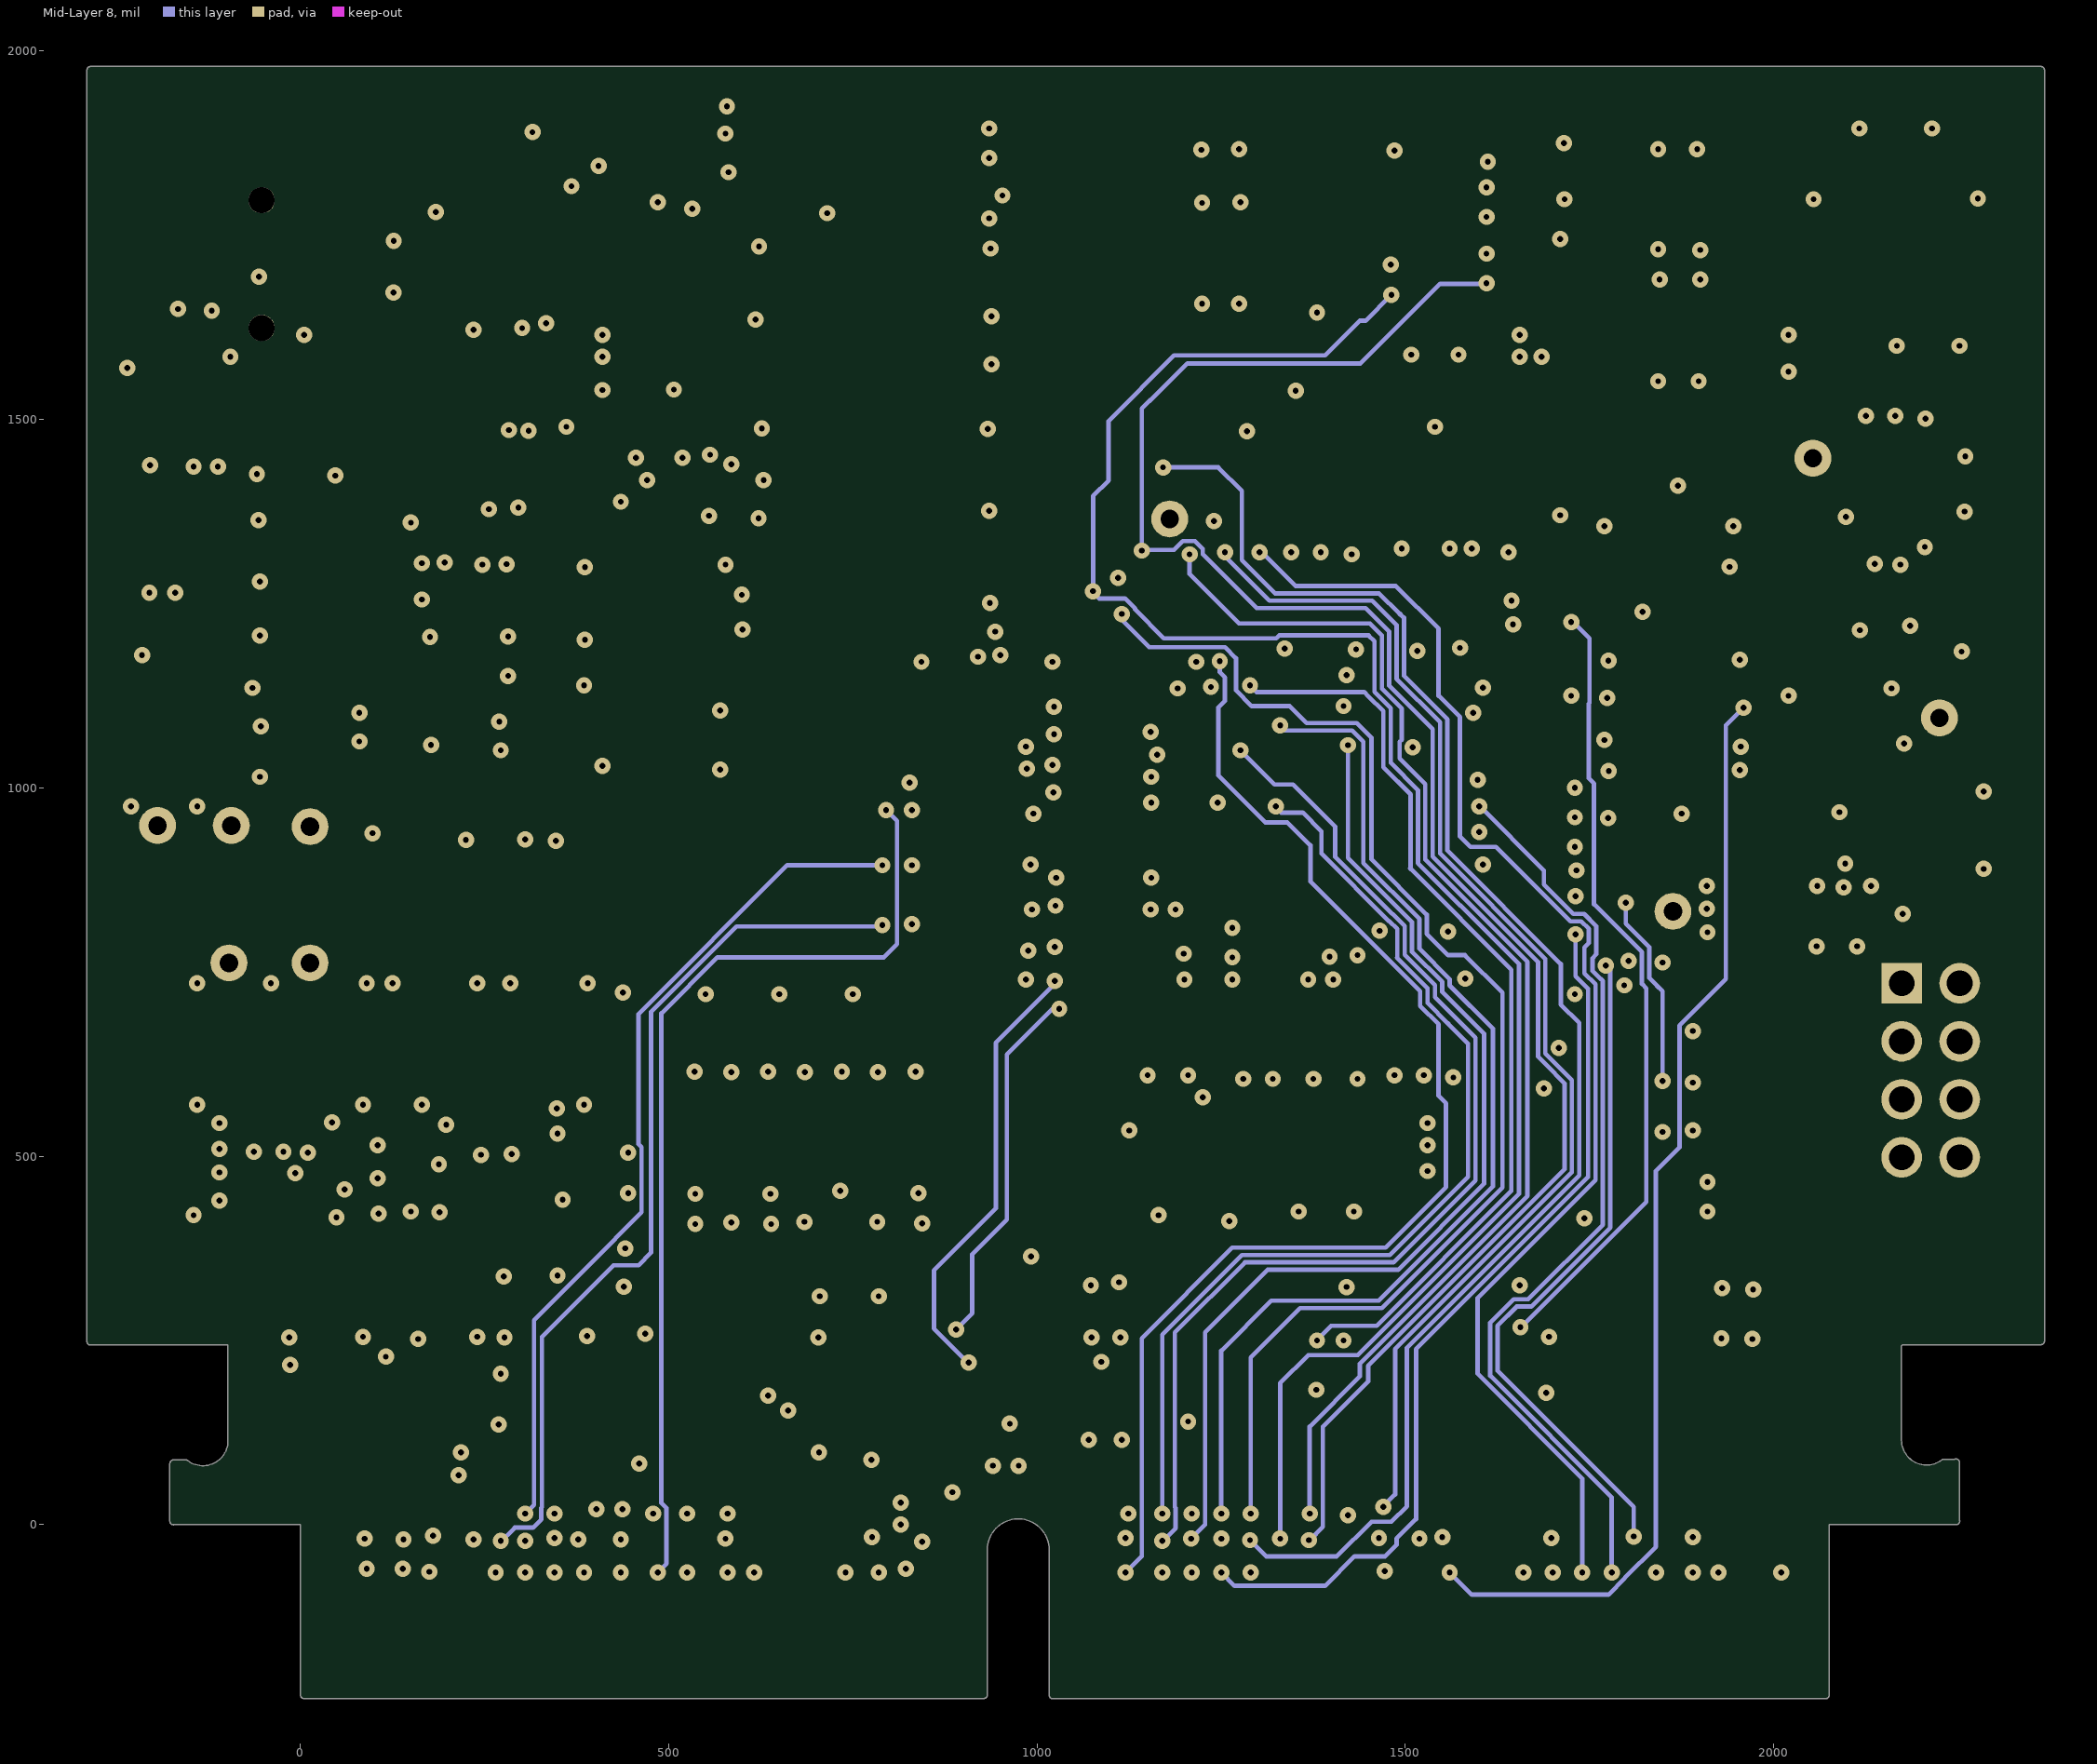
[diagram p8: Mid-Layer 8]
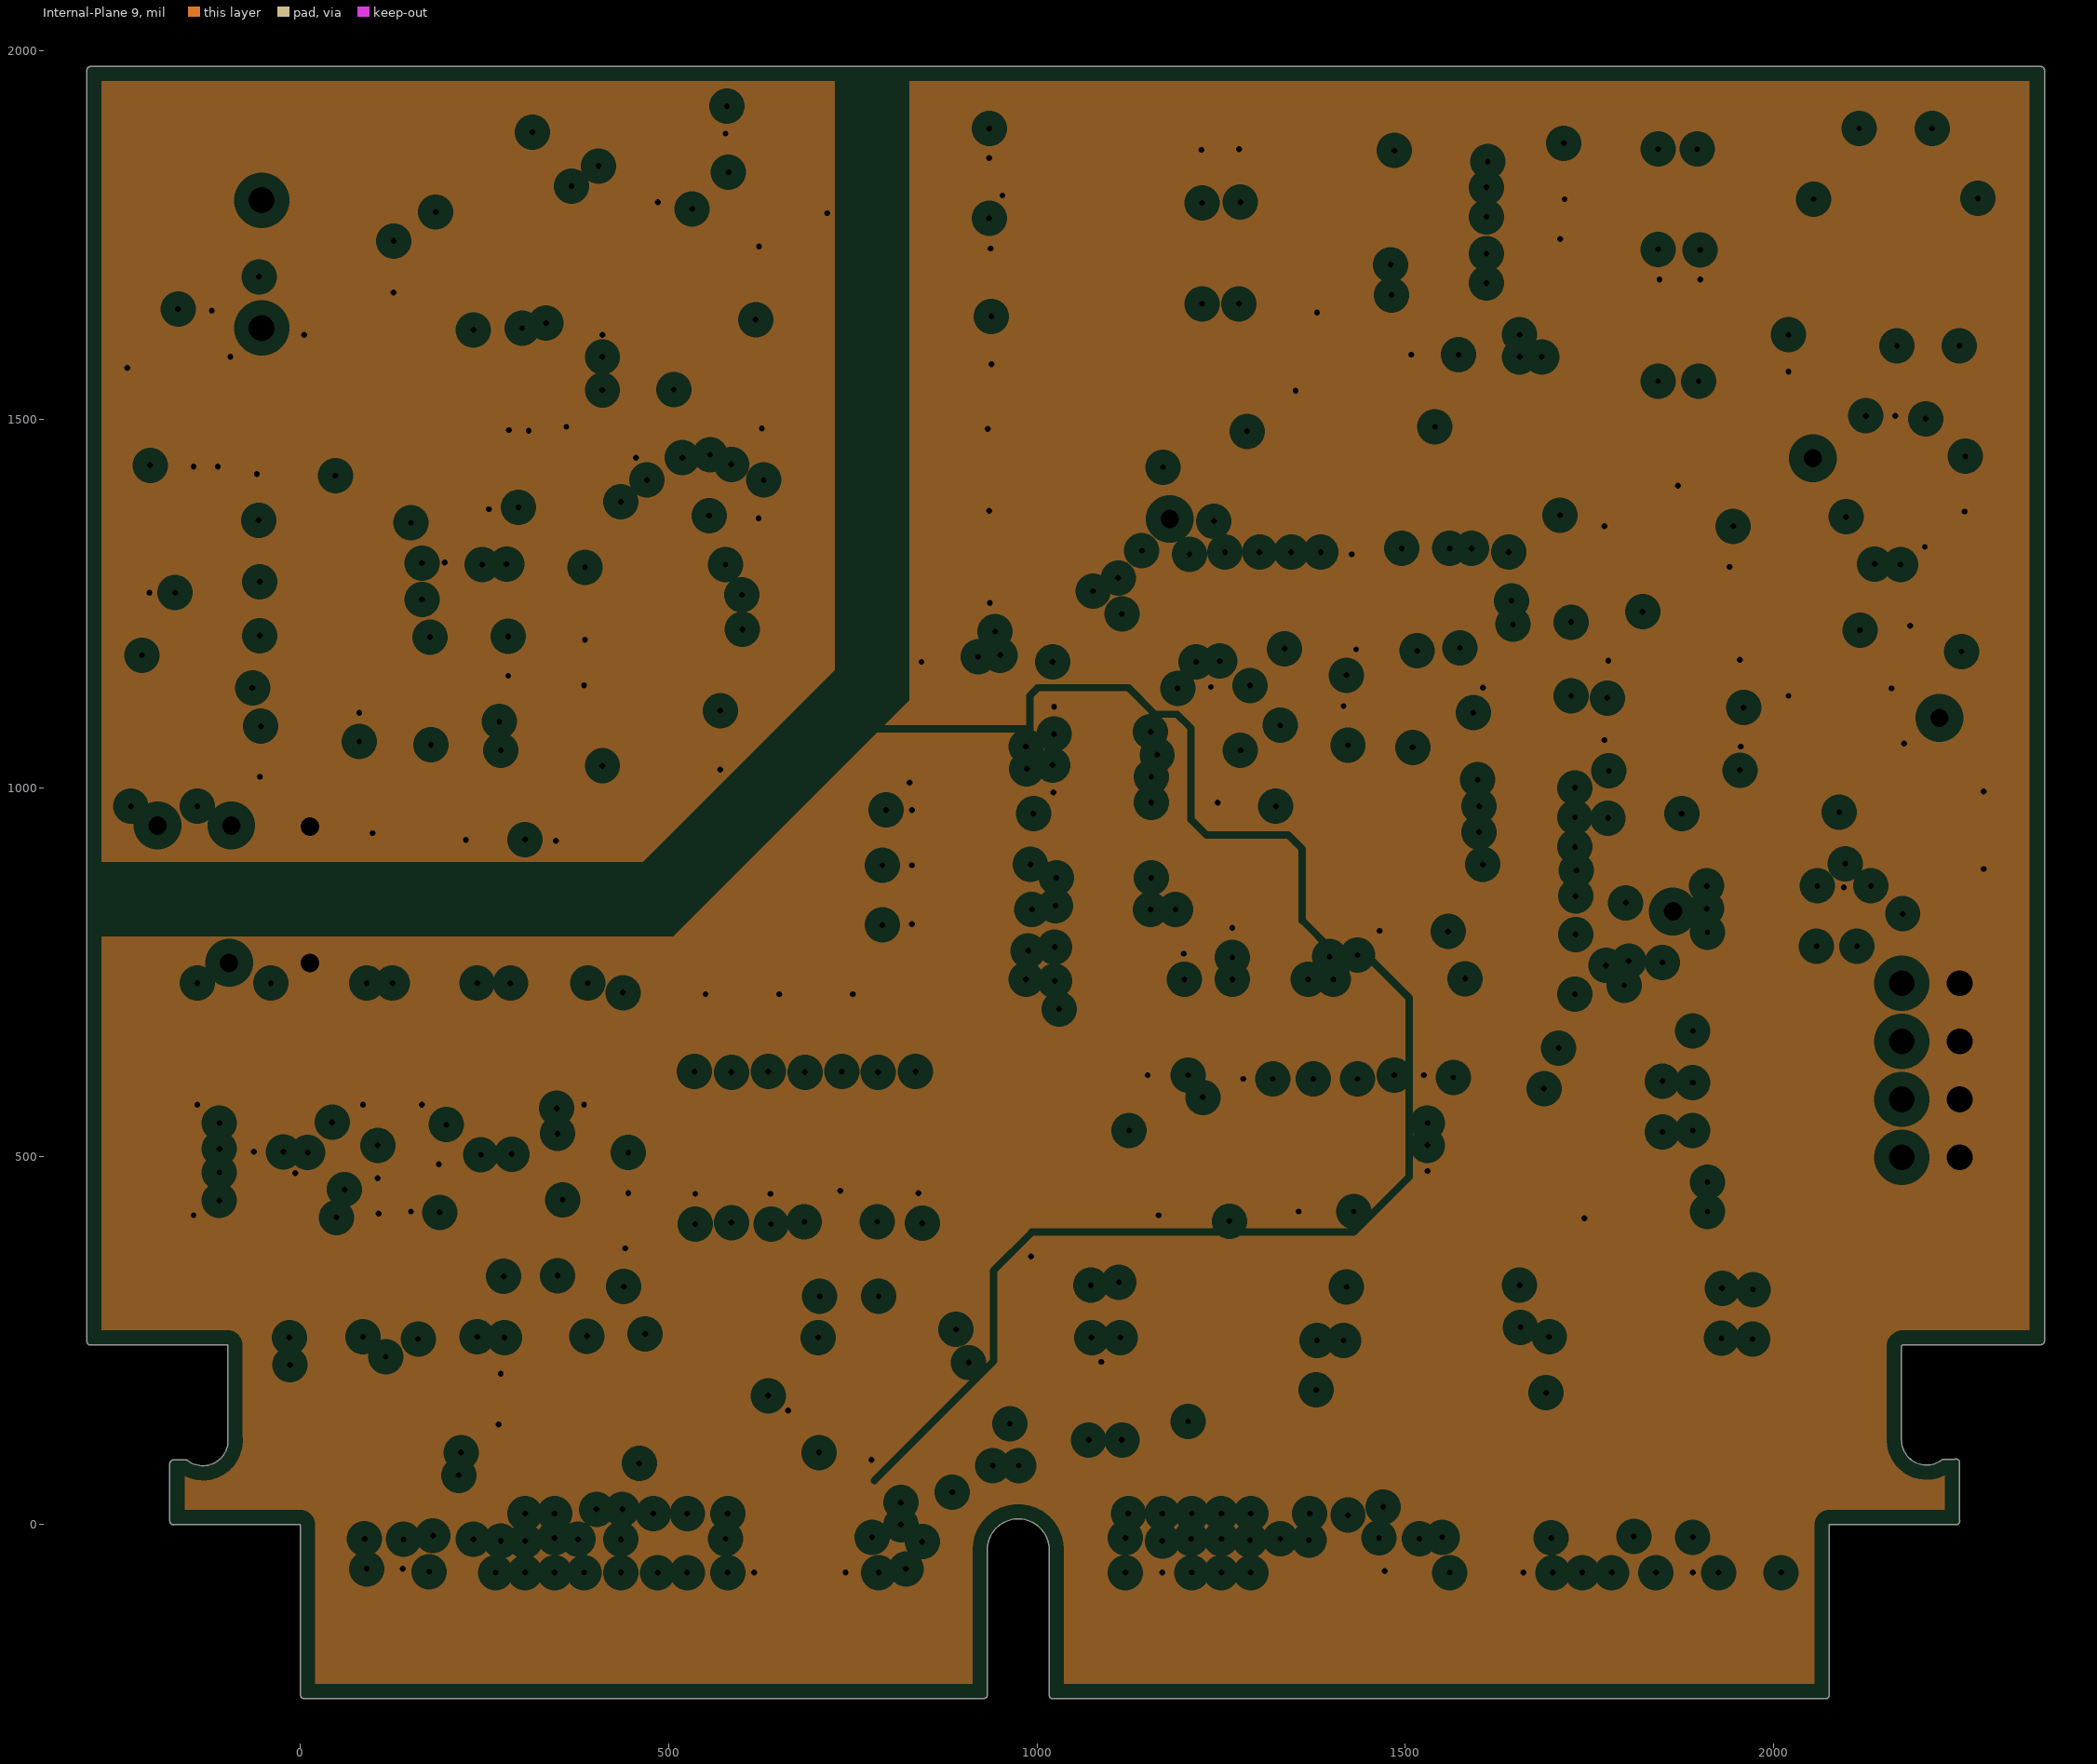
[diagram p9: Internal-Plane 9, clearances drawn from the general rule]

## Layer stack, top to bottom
Top Solder: solder mask 0.5, Solder Resist, Dk 3.5
Top Layer: signal copper 1.4
Dielectric1: core 5.2, FR-4, Dk 4.8
Internal-Plane 2: plane copper 1.4, net (Multiple Nets)
Dielectric6: dielectric 5.2, FR-4, Dk 4.8
Mid-Layer 3: signal copper 1.4
Dielectric2: dielectric 5.2, FR-4, Dk 4.8
Mid-Layer 4: signal copper 1.4
Dielectric3: dielectric 5.2, FR-4, Dk 4.8
Internal-Plane 5: plane copper 1.4, net (Multiple Nets)
Dielectric8: dielectric 5.2, FR-4, Dk 4.8
Internal-Plane 6: plane copper 1.4, net (Multiple Nets)
Dielectric7: dielectric 5.2, FR-4, Dk 4.8
Mid-Layer 7: signal copper 1.4
Dielectric5: dielectric 5.2, FR-4, Dk 4.8
Mid-Layer 8: signal copper 1.4
Dielectric4: dielectric 5.2, FR-4, Dk 4.8
Internal-Plane 9: plane copper 1.4, net (Multiple Nets)
Dielectric9: dielectric 5.2, FR-4, Dk 4.8
Bottom Layer: signal copper 1.4
Bottom Solder: solder mask 0.5, Solder Resist, Dk 3.5

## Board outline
-177.19,4.84 ccw(c-172.18,4.84) -171.01,-0.04 0.06,-0.04 0.06,-231.05 ccw(c5.07,-231.05) 5.9,-236 927.51,-236 ccw(c927.51,-230.98) 932.53,-230.98 ccw(c927.51,-230.98) 932.32,-229.56 932.32,-35.08 932.42,-34.1 cw(c974.4,-34.1) 1016.39,-34.1 1016.39,-231.27 ccw(c1021.4,-231.27) 1017.86,-234.81 1017.92,-234.88 ccw(c1021.47,-231.33) 1021.47,-236.35 1034.75,-236.35 1035.58,-236.28 2070.22,-236.28 ccw(c2070.22,-231.26) 2075.23,-231.26 2075.16,-230.44 2075.16,-0.11 2247.39,-0.11 ccw(c2247.39,4.91) 2252.41,4.91 ccw(c2247.39,4.91) 2252.2,6.33 2252.2,84.13 ccw(c2247.19,84.13) 2245.21,88.74 2230.93,88.74 ccw(c2230.93,83.73) 2227.9,87.73 cw(c2207.4,114.83) 2173.42,114.71 2173.42,242.73 2174.88,244.19 2362.35,244.19 ccw(c2362.35,249.21) 2365.9,245.66 2365.96,245.72 ccw(c2362.41,249.27) 2367.42,249.27 2367.42,1973.27 2367.49,1974.1 ccw(c2362.48,1974.1) 2362.48,1979.11 -284.69,1979.11 ccw(c-284.69,1974.1) -288.23,1977.64 -288.26,1977.62 ccw(c-284.72,1974.07) -289.73,1974.07 -289.73,248.71 ccw(c-284.72,248.71) -284.72,243.7 -98.73,243.7 -98.73,238.74 ccw(c-93.71,238.74) -98.32,236.75 -98.32,115.84 -98.31,115.56 cw(c-132.26,113.93) -98.27,113.93 cw(c-132.26,113.93) -152.76,86.83 ccw(c-155.78,82.83) -155.78,87.84 -172.11,87.84 ccw(c-172.11,82.83) -175.66,86.37 -175.72,86.31 ccw(c-172.18,82.76) -177.19,82.76

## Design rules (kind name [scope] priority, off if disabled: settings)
AcuteAngle [All] p0: scope1count=1 scope1_0_kind=Board scope1_0_value=Board scope2count=1 scope2_0_kind=Board scope2_0_value=Board commentlength=0 minimum=4.50000000000000E+0001
AcuteAngle [All] p1: minimum=4.50000000000000E+0001 checktracksonly=FALSE
AssemblyTestPointUsage [All] p0: scope1count=1 scope1_0_kind=Board scope1_0_value=Board scope2count=1 scope2_0_kind=Board scope2_0_value=Board commentlength=0
AssemblyTestPointUsage [All] p1: valid=2
AssemblyTestpoint [All] p0: scope1count=1 scope1_0_kind=Board scope1_0_value=Board scope2count=1 scope2_0_kind=Board scope2_0_value=Board commentlength=0
BoardOutlineClearance [All] p0 off: scope1count=1 scope1_0_kind=Board scope1_0_value=Board scope2count=1 scope2_0_kind=Board scope2_0_value=Board commentlength=202 gap=40 // Protel DXP Scope 1 Expression Was: OnCopper and Not InComponentClass('Logo') and not InComponentClass('FiducialMark') and not InComponent ('EC1') and not InPoly and not InRegion(-350,-150,2400,2025)
BoardOutlineClearance BoardOutlineClearance_Poly [All] p0 off: scope1count=1 scope1_0_kind=Board scope1_0_value=Board scope2count=1 scope2_0_kind=Board scope2_0_value=Board commentlength=58 gap=25 // Protel DXP Scope 1 Expression Was: OnCopper and IsPoly
BoardOutlineClearance BoardOutlineClearance_MountingHoles [All] p0 off: scope1count=1 scope1_0_kind=Board scope1_0_value=Board scope2count=1 scope2_0_kind=Board scope2_0_value=Board commentlength=86 gap=40 // Protel DXP Scope 1 Expression Was: OnCopper and InComponentClass('Mounting Holes')
BoardOutlineClearance BoardOutlineClearance_MountingHoles [OnCopper and InComponentClass('Mounting Holes')] p1: gap=40 ignorepadtopadclearanceinfootprint=FALSE
BoardOutlineClearance BoardOutlineClearance_Poly [OnCopper and IsPoly] p2: gap=25 ignorepadtopadclearanceinfootprint=FALSE
BoardOutlineClearance [OnCopper and Not InComponentClass('Logo') and not InComponentClass('FiducialMark') and not InComponent ('EC1') and not InPoly and not InRegion(-350,-150,2400,2025)] p3: gap=40 ignorepadtopadclearanceinfootprint=FALSE
Clearance [All] p0: scope1count=1 scope1_0_kind=Board scope1_0_value=Board scope2count=1 scope2_0_kind=Board scope2_0_value=Board commentlength=0 gap=4
Clearance Clearance_Fiducial [All] p0: scope1count=1 scope1_0_kind=Footprint scope1_0_value=Fiducial10-20 scope2count=1 scope2_0_kind=Board scope2_0_value=Board commentlength=0 gap=4
Clearance Clearance_Poly [All] p0 off: scope1count=1 scope1_0_kind=Board scope1_0_value=Board scope2count=1 scope2_0_kind=Board scope2_0_value=Board commentlength=48 gap=6 // Protel DXP Scope 1 Expression Was: InPolygon
Clearance Clearance_Keepouts [All] p0 off: scope1count=1 scope1_0_kind=Board scope1_0_value=Board scope2count=1 scope2_0_kind=Board scope2_0_value=Board commentlength=99 gap=0 // Protel DXP Scope 2 Expression Was: ((IsTrack Or IsArc) And Not InPoly) And IsFree and IsKeepOut
Clearance Clearance_Boardedge_Poly [All] p0 off: scope1count=1 scope1_0_kind=Board scope1_0_value=Board scope2count=1 scope2_0_kind=Board scope2_0_value=Board commentlength=48 gap=25 // Protel DXP Scope 2 Expression Was: IsKeepOut
Clearance Clearance_Boardedge [All] p0 off: scope1count=1 scope1_0_kind=Board scope1_0_value=Board scope2count=1 scope2_0_kind=Board scope2_0_value=Board commentlength=48 gap=10 // Protel DXP Scope 2 Expression Was: IsKeepOut
Clearance Clearance_Boardedge_MountingHole [All] p0 off: scope1count=1 scope1_0_kind=Board scope1_0_value=Board scope2count=1 scope2_0_kind=Board scope2_0_value=Board commentlength=48 gap=30 // Protel DXP Scope 2 Expression Was: IsKeepOut
Clearance Clearance_Keepouts [((IsTrack Or IsArc) And Not InPoly) And IsFree and IsKeepOut vs ((IsTrack Or IsArc) And Not InPoly) And IsFree and IsKeepOut] p1: gap=0 ignorepadtopadclearanceinfootprint=FALSE
Clearance Clearance_Boardedge_MountingHole [OnCopper and InComponentClass('Mounting Holes') vs IsKeepOut] p2: gap=30 ignorepadtopadclearanceinfootprint=FALSE except(0: Arc-Hole Track-Hole SMDPad-Hole THPad-Hole Via-Hole Fill-Hole Poly-Hole Region-Hole Text-Hole)
Clearance Clearance_Boardedge_Poly [OnCopper and InPoly vs IsKeepOut] p3: gap=25 ignorepadtopadclearanceinfootprint=FALSE except(0: Arc-Hole Track-Hole SMDPad-Hole THPad-Hole Via-Hole Fill-Hole Poly-Hole Region-Hole Text-Hole)
Clearance Clearance_Boardedge [OnCopper and Not InComponentClass('Logo') and not InComponentClass('FiducialMark') and not Incomponent ('EC1') and Not IsKeepout vs IsKeepOut] p4: gap=10 ignorepadtopadclearanceinfootprint=FALSE except(0: Arc-Hole Track-Hole SMDPad-Hole THPad-Hole Via-Hole Fill-Hole Poly-Hole Region-Hole Text-Hole)
Clearance Clearance_Poly [InPolygon] p5: gap=6 ignorepadtopadclearanceinfootprint=FALSE except(0: Arc-Hole Track-Hole SMDPad-Hole THPad-Hole Via-Hole Fill-Hole Poly-Hole Region-Hole Text-Hole)
Clearance Clearance_Fiducial [HasFootprint('Fiducial10-20')] p6: gap=4 ignorepadtopadclearanceinfootprint=TRUE except(0: Arc-SMDPad Arc-Hole Track-Hole SMDPad-Hole THPad-Hole Via-Hole Fill-Hole Poly-Hole Region-Hole Text-Hole)
Clearance [All] p7: gap=4 ignorepadtopadclearanceinfootprint=TRUE except(0: Arc-Hole Track-Hole SMDPad-Hole THPad-Hole Via-Hole Fill-Hole Poly-Hole Region-Hole Text-Hole)
ComponentClearance [All] p0: scope1count=1 scope1_0_kind=Board scope1_0_value=Board scope2count=1 scope2_0_kind=Board scope2_0_value=Board commentlength=0 gap=30 collisioncheckmode=3
ComponentClearance ComponentClearance_THtoTH [All] p0 off: scope1count=1 scope1_0_kind=Board scope1_0_value=Board scope2count=1 scope2_0_kind=Board scope2_0_value=Board commentlength=54 gap=30 collisioncheckmode=3 // Protel DXP Scope 2 Expression Was: IsThruComponent
ComponentClearance ComponentClearance_THtoSMT [All] p0 off: scope1count=1 scope1_0_kind=Board scope1_0_value=Board scope2count=1 scope2_0_kind=Board scope2_0_value=Board commentlength=161 gap=40 collisioncheckmode=3 // Protel DXP Scope 2 Expression Was: IsSMTComponent and not Incomponent ('J1') and not Incomponent ('J2') and not Incomponent ('J3') and not Incomponent ('J4')
ComponentClearance ComponentClearance_SmallPassives [All] p0 off: scope1count=1 scope1_0_kind=Board scope1_0_value=Board scope2count=1 scope2_0_kind=Board scope2_0_value=Board commentlength=508 gap=10 collisioncheckmode=3 // Protel DXP Scope 2 Expression Was: HasFootprint('0201*') or HasFootprint('0402*') or HasFootprint('0508') or HasFootprint('0603*') or HasFootprint('0612') or HasFootprint('0805*') or HasFootprint('0815*') or HasFootprint('0830*') or HasFootprint('1206*') or HasFootprint('1210*') or HasFootprint('1808*') or HasFootprint('1812*') or HasFootprint('1825*') or HasFootprint('2010*') or HasFootprint('2220*') or HasFootprint('2225*') or HasFootprint('2512*') or HasFootprint('2728*') or HasFootprint('3518*')
ComponentClearance ComponentClearance_MountingHoles [All] p0: scope1count=1 scope1_0_kind=ComponentClass scope1_0_value="Mounting Holes" scope2count=1 scope2_0_kind=Board scope2_0_value=Board commentlength=0 gap=250 collisioncheckmode=3
ComponentClearance ComponentClearance_ScrewToNut [All] p0 off: scope1count=1 scope1_0_kind=Board scope1_0_value=Board scope2count=1 scope2_0_kind=Board scope2_0_value=Board commentlength=71 gap=5 collisioncheckmode=3 // Protel DXP Scope 2 Expression Was: (HasFootprint('Keystone_1902C'))
ComponentClearance ComponentClearance_Logo [All] p0: scope1count=1 scope1_0_kind=ComponentClass scope1_0_value=Logo scope2count=1 scope2_0_kind=Board scope2_0_value=Board commentlength=0 gap=50 collisioncheckmode=3
ComponentClearance ComponentClearance_Shunt [All] p0: scope1count=1 scope1_0_kind=ComponentClass scope1_0_value=Header scope2count=1 scope2_0_kind=ComponentClass scope2_0_value=Shunt commentlength=0 gap=0 collisioncheckmode=3
ComponentClearance ComponentClearance_MountingHoles_FiducialMarks [All] p0: scope1count=1 scope1_0_kind=ComponentClass scope1_0_value="Mounting Holes" scope2count=1 scope2_0_kind=ComponentClass scope2_0_value=FiducialMark commentlength=0 gap=50 collisioncheckmode=3
ComponentClearance ComponentClearance_MountingHoles_FiducialMarks [InComponentClass('Mounting Holes') vs InComponentClass('FiducialMark')] p1: gap=50 collisioncheckmode=3 verticalgap=10 showdistances=FALSE
ComponentClearance ComponentClearance_Shunt [InComponentClass('Header') vs InComponentClass('Shunt')] p2: gap=0 collisioncheckmode=3 verticalgap=0 showdistances=FALSE
ComponentClearance ComponentClearance_Logo [InComponentClass('Logo')] p3: gap=50 collisioncheckmode=3 verticalgap=10 showdistances=FALSE
ComponentClearance ComponentClearance_ScrewToNut [(HasFootprint('NY PMS 440 0025 PH')) vs (HasFootprint('Keystone_1902C'))] p4: gap=5 collisioncheckmode=3 verticalgap=10 showdistances=FALSE
ComponentClearance ComponentClearance_MountingHoles [InComponentClass('Mounting Holes')] p5: gap=250 collisioncheckmode=3 verticalgap=100000 showdistances=FALSE
ComponentClearance ComponentClearance_SmallPassives [HasFootprint('0201*') or HasFootprint('0402*') or HasFootprint('0508') or HasFootprint('0603*') or HasFootprint('0612') or HasFootprint('0805*') or HasFootprint('0815*') or HasFootprint('0830*') or HasFootprint('1206*') or HasFootprint('1210*') or HasFootprint('1808*') or HasFootprint('1812*') or HasFootprint('1825*') or HasFootprint('2010*') or HasFootprint('2220*') or HasFootprint('2225*') or HasFootprint('2512*') or HasFootprint('2728*') or HasFootprint('3518*') vs HasFootprint('0201*') or HasFootprint('0402*') or HasFootprint('0508') or HasFootprint('0603*') or HasFootprint('0612') or HasFootprint('0805*') or HasFootprint('0815*') or HasFootprint('0830*') or HasFootprint('1206*') or HasFootprint('1210*') or HasFootprint('1808*') or HasFootprint('1812*') or HasFootprint('1825*') or HasFootprint('2010*') or HasFootprint('2220*') or HasFootprint('2225*') or HasFootprint('2512*') or HasFootprint('2728*') or HasFootprint('3518*')] p6: gap=10 collisioncheckmode=3 verticalgap=10 showdistances=FALSE
ComponentClearance ComponentClearance_THtoSMT [IsThruComponent vs IsSMTComponent and not Incomponent ('J1') and not Incomponent ('J2') and not Incomponent ('J3') and not Incomponent ('J4')] p7: gap=40 collisioncheckmode=3 verticalgap=30 showdistances=FALSE
ComponentClearance ComponentClearance_THtoTH [IsThruComponent vs IsThruComponent] p8: gap=30 collisioncheckmode=3 verticalgap=30 showdistances=FALSE
ComponentClearance [All] p9: gap=30 collisioncheckmode=3 verticalgap=10 showdistances=FALSE
DiffPairsRouting [All] p0: scope1count=1 scope1_0_kind=Board scope1_0_value=Board scope2count=1 scope2_0_kind=Board scope2_0_value=Board commentlength=0
DiffPairsRouting [All] p1: maxlimit=100 minlimit=10 mostfreqgap=10 toplayer_minwidth=15 toplayer_maxwidth=15 toplayer_prefwidth=15 midlayer1_minwidth=15 midlayer1_maxwidth=15 midlayer1_prefwidth=15 midlayer2_minwidth=15 midlayer2_maxwidth=15 midlayer2_prefwidth=15 midlayer3_minwidth=15 midlayer3_maxwidth=15 midlayer3_prefwidth=15 midlayer4_minwidth=15 midlayer4_maxwidth=15 midlayer4_prefwidth=15 bottomlayer_minwidth=15 bottomlayer_maxwidth=15 bottomlayer_prefwidth=15 maxuncoupledlength=1000
FabricationTestPointUsage TestPointUsage [All] p0: scope1count=1 scope1_0_kind=Board scope1_0_value=Board scope2count=1 scope2_0_kind=Board scope2_0_value=Board commentlength=0 valid=2 allowmultiple=FALSE
FabricationTestPointUsage TestPointUsage [All] p1: valid=2 allowmultiple=FALSE
FabricationTestpoint Testpoint [All] p0: scope1count=1 scope1_0_kind=Board scope1_0_value=Board scope2count=1 scope2_0_kind=Board scope2_0_value=Board commentlength=0 side=3 testpointundercomponent=TRUE minsize=40 maxsize=100 preferedsize=60 minholesize=0 maxholesize=40 preferedholesize=32 testpointgrid=1
FabricationTestpoint Testpoint [All] p1: side=3 testpointundercomponent=TRUE minsize=40 maxsize=100 preferedsize=60 minholesize=0 maxholesize=40 preferedholesize=32 testpointgrid=1 allowsidetop=TRUE allowsidebottom=TRUE usegrid=TRUE gridtolerance=0.01
FanoutControl Fanout_Small [All] p0 off: scope1count=1 scope1_0_kind=Board scope1_0_value=Board scope2count=1 scope2_0_kind=Board scope2_0_value=Board commentlength=84 // Protel DXP Scope 1 Expression Was: (CompPinCount < 5)   Fanout_Small (Default Rule)
FanoutControl Fanout_Default [All] p0: scope1count=1 scope1_0_kind=Board scope1_0_value=Board scope2count=1 scope2_0_kind=Board scope2_0_value=Board commentlength=30 // Fanout_Default (Default Rule)
FanoutControl Fanout_SOIC [All] p0 off: scope1count=1 scope1_0_kind=Board scope1_0_value=Board scope2count=1 scope2_0_kind=Board scope2_0_value=Board commentlength=71 // Protel DXP Scope 1 Expression Was: IsSOIC   Fanout_SOIC (Default Rule)
FanoutControl Fanout_BGA [All] p0 off: scope1count=1 scope1_0_kind=Board scope1_0_value=Board scope2count=1 scope2_0_kind=Board scope2_0_value=Board commentlength=69 // Protel DXP Scope 1 Expression Was: IsBGA   Fanout_BGA (Default Rule)
FanoutControl Fanout_LCC [All] p0 off: scope1count=1 scope1_0_kind=Board scope1_0_value=Board scope2count=1 scope2_0_kind=Board scope2_0_value=Board commentlength=69 // Protel DXP Scope 1 Expression Was: IsLCC   Fanout_LCC (Default Rule)
FanoutControl Fanout_LCC [IsLCC] p1: bgadir=Out bgaviamode=Centered fanoutstyle=Auto fanoutdirection=Alternating viagrid=1 // Fanout_LCC (Default Rule)
FanoutControl Fanout_BGA [IsBGA] p2: bgadir=Out bgaviamode=Centered fanoutstyle=Auto fanoutdirection=Alternating viagrid=1 // Fanout_BGA (Default Rule)
FanoutControl Fanout_Default [All] p4: bgadir=Out bgaviamode=Centered fanoutstyle=Auto fanoutdirection=Alternating viagrid=1 // Fanout_Default (Default Rule)
FanoutControl Fanout_Small [(CompPinCount < 5)] p5: bgadir=Out bgaviamode=Centered fanoutstyle=Auto fanoutdirection=OutThenIn viagrid=1 // Fanout_Small (Default Rule)
Height [All] p0: scope1count=1 scope1_0_kind=Board scope1_0_value=Board scope2count=1 scope2_0_kind=Board scope2_0_value=Board commentlength=0
HoleSize [All] p0: scope1count=1 scope1_0_kind=Board scope1_0_value=Board scope2count=1 scope2_0_kind=Board scope2_0_value=Board commentlength=0 absolutevalues=TRUE maxlimit=251 minlimit=7.87 maxpercent=80.000 minpercent=20.000
HoleSize [All] p1: absolutevalues=TRUE maxlimit=251 minlimit=7.87 maxpercent=80.000 minpercent=20.000
HoleToHoleClearance [All] p0: scope1count=1 scope1_0_kind=Board scope1_0_value=Board scope2count=1 scope2_0_kind=Board scope2_0_value=Board commentlength=0
LayerPairs [All] p0: scope1count=1 scope1_0_kind=Board scope1_0_value=Board scope2count=1 scope2_0_kind=Board scope2_0_value=Board commentlength=0 enforce=TRUE
MinimumAnnularRing [All] p0: scope1count=1 scope1_0_kind=Board scope1_0_value=Board scope2count=1 scope2_0_kind=Board scope2_0_value=Board commentlength=0 minimumring=7
MinimumAnnularRing MinimumAnnularRing_ThermalPadVias [All] p0 off: scope1count=1 scope1_0_kind=Board scope1_0_value=Board scope2count=1 scope2_0_kind=Board scope2_0_value=Board commentlength=63 minimumring=5.91 // Protel DXP Scope 1 Expression Was: IsVia and InAnyComponent
MinimumAnnularRing MinimumAnnularRing_ThermalPadVias [IsVia and InAnyComponent] p1: minimumring=5.91
MinimumAnnularRing [All] p2: minimumring=7
MinimumSolderMaskSliver [All] p0: scope1count=1 scope1_0_kind=Board scope1_0_value=Board scope2count=1 scope2_0_kind=Board scope2_0_value=Board commentlength=0
MinimumSolderMaskSliver MinimumSolderMaskSliver_Logo [All] p0: scope1count=1 scope1_0_kind=ComponentClass scope1_0_value=Logo scope2count=1 scope2_0_kind=ComponentClass scope2_0_value=Logo commentlength=0
MinimumSolderMaskSliver MinimumSolderMaskSliver_Logo [InComponentClass('Logo') vs InComponentClass('Logo')] p1: minsoldermaskwidth=0.7
MinimumSolderMaskSliver [All] p2: minsoldermaskwidth=3.94
NetAntennae [All] p0: scope1count=1 scope1_0_kind=Board scope1_0_value=Board scope2count=1 scope2_0_kind=Board scope2_0_value=Board commentlength=0
PasteMaskExpansion [All] p0: scope1count=1 scope1_0_kind=Board scope1_0_value=Board scope2count=1 scope2_0_kind=Board scope2_0_value=Board commentlength=0 expansion=0
PlaneClearance PlaneClearance_Via [All] p0 off: scope1count=1 scope1_0_kind=Board scope1_0_value=Board scope2count=1 scope2_0_kind=Board scope2_0_value=Board commentlength=44 clearance=15 // Protel DXP Scope 1 Expression Was: IsVia
PlaneClearance [All] p0: scope1count=1 scope1_0_kind=Board scope1_0_value=Board scope2count=1 scope2_0_kind=Board scope2_0_value=Board commentlength=0 clearance=20
PlaneClearance PlaneClearance_Via [IsVia] p1: clearance=15
PlaneClearance [All] p2: clearance=20
PlaneConnect [All] p0: scope1count=1 scope1_0_kind=Board scope1_0_value=Board scope2count=1 scope2_0_kind=Board scope2_0_value=Board commentlength=0 planeconnectstyle=Relief reliefexpansion=10 reliefentries=4 reliefconductorwidth=10 reliefairgap=10
PlaneConnect [All] p1: planeconnectstyle=Relief reliefexpansion=10 reliefentries=4 reliefconductorwidth=10 reliefairgap=10
PolygonConnect [All] p0: scope1count=1 scope1_0_kind=Board scope1_0_value=Board scope2count=1 scope2_0_kind=Board scope2_0_value=Board commentlength=0 connectstyle=Relief reliefconductorwidth=10 reliefentries=4 polygonreliefangle="90 Angle"
PolygonConnect PolygonConnect_via [All] p0 off: scope1count=1 scope1_0_kind=Board scope1_0_value=Board scope2count=1 scope2_0_kind=Board scope2_0_value=Board commentlength=44 connectstyle=Direct reliefconductorwidth=10 reliefentries=4 polygonreliefangle="90 Angle" // Protel DXP Scope 1 Expression Was: isvia
PolygonConnect PolygonConnect_via [isvia] p1: connectstyle=Direct reliefconductorwidth=10 reliefentries=4 polygonreliefangle="90 Angle" airgapwidth=10
PolygonConnect [All] p2: connectstyle=Relief reliefconductorwidth=10 reliefentries=4 polygonreliefangle="90 Angle" airgapwidth=10
RoutingCorners [All] p0: scope1count=1 scope1_0_kind=Board scope1_0_value=Board scope2count=1 scope2_0_kind=Board scope2_0_value=Board commentlength=0 cornerstyle=45-Degree minsetback=100 maxsetback=100
RoutingLayers [All] p0: scope1count=1 scope1_0_kind=Board scope1_0_value=Board scope2count=1 scope2_0_kind=Board scope2_0_value=Board commentlength=0 top layer=Automatic mid layer 1=Automatic mid layer 2=Automatic mid layer 3=Automatic mid layer 4=Automatic bottom layer=Automatic
RoutingPriority [All] p0: scope1count=1 scope1_0_kind=Board scope1_0_value=Board scope2count=1 scope2_0_kind=Board scope2_0_value=Board commentlength=0
RoutingTopology [All] p0: scope1count=1 scope1_0_kind=Board scope1_0_value=Board scope2count=1 scope2_0_kind=Board scope2_0_value=Board commentlength=0 topology=Shortest
RoutingVias [All] p0: scope1count=1 scope1_0_kind=Board scope1_0_value=Board scope2count=1 scope2_0_kind=Board scope2_0_value=Board commentlength=0 holewidth=8 width=22 viastyle="Through Hole" minholewidth=8 minwidth=22 maxholewidth=40 maxwidth=65
RoutingVias ThermalPadVias [All] p0 off: scope1count=1 scope1_0_kind=Board scope1_0_value=Board scope2count=1 scope2_0_kind=Board scope2_0_value=Board commentlength=63 holewidth=8 width=22 viastyle="Through Hole" minholewidth=8 minwidth=22 maxholewidth=12.99 maxwidth=23.62 // Protel DXP Scope 1 Expression Was: IsVia and InAnyComponent
RoutingVias ThermalPadVias [IsVia and InAnyComponent] p1: holewidth=8 width=22 viastyle="Through Hole" minholewidth=8 minwidth=22 maxholewidth=12.99 maxwidth=23.62
RoutingVias [All] p2: holewidth=8 width=22 viastyle="Through Hole" minholewidth=8 minwidth=22 maxholewidth=40 maxwidth=65
ShortCircuit [All] p0: scope1count=1 scope1_0_kind=Board scope1_0_value=Board scope2count=1 scope2_0_kind=Board scope2_0_value=Board commentlength=0 allowed=FALSE
SilkToBoardRegionClearance [All] p0 off: scope1count=1 scope1_0_kind=Board scope1_0_value=Board scope2count=1 scope2_0_kind=Board scope2_0_value=Board commentlength=130 // Protel DXP Scope 1 Expression Was: Not ((IsComment or IsDesignator) And (Hide <> 'False')) and not InRegion(1000,500,4000,800)
SilkToBoardRegionClearance [Not ((IsComment or IsDesignator) And (Hide <> 'False')) and not InRegion(1000,500,4000,800)] p1:
SilkToSilkClearance [All] p0: scope1count=1 scope1_0_kind=Board scope1_0_value=Board scope2count=1 scope2_0_kind=Board scope2_0_value=Board commentlength=0
SilkToSilkClearance SilkToSilkClearance_Pb-FreeLogo [All] p0 off: scope1count=1 scope1_0_kind=Board scope1_0_value=Board scope2count=1 scope2_0_kind=Board scope2_0_value=Board commentlength=120 // Protel DXP Scope 2 Expression Was: (HasFootprint('Pb-Free_Overlay_Medium') OR HasFootprint('Pb-Free_Overlay_Small'))
SilkToSilkClearance SilkToSilkClearance_Pb-FreeLogo [(HasFootprint('Pb-Free_Overlay_Medium') OR HasFootprint('Pb-Free_Overlay_Small')) vs (HasFootprint('Pb-Free_Overlay_Medium') OR HasFootprint('Pb-Free_Overlay_Small'))] p1: silktosilkclearance=0
SilkToSilkClearance [All] p2: silktosilkclearance=3
SilkToSolderMaskClearance "Silk to Solder Mask Opening" [All] p0: scope1count=1 scope1_0_kind=Board scope1_0_value=Board scope2count=1 scope2_0_kind=Board scope2_0_value=Board commentlength=0
SilkToSolderMaskClearance SilkToComponentPadClearance [All] p0 off: scope1count=1 scope1_0_kind=Board scope1_0_value=Board scope2count=1 scope2_0_kind=Board scope2_0_value=Board commentlength=63 // Protel DXP Scope 1 Expression Was: IsPad and InAnycomponent
SilkToSolderMaskClearance SilkToComponentPadClearance [IsPad and InAnycomponent] p1: minsilkscreentomaskgap=3 clearancetoexposedcopper=TRUE
SilkToSolderMaskClearance "Silk to Solder Mask Opening" [All] p2: minsilkscreentomaskgap=3 clearancetoexposedcopper=FALSE
SolderMaskExpansion [All] p0: scope1count=1 scope1_0_kind=Board scope1_0_value=Board scope2count=1 scope2_0_kind=Board scope2_0_value=Board commentlength=0 expansion=1.97
SolderMaskExpansion [All] p1: expansion=1.97
UnRoutedNet [All] p0: scope1count=1 scope1_0_kind=Board scope1_0_value=Board scope2count=1 scope2_0_kind=Board scope2_0_value=Board commentlength=0
UnpouredPolygon [All] p0: scope1count=1 scope1_0_kind=Board scope1_0_value=Board scope2count=1 scope2_0_kind=Board scope2_0_value=Board commentlength=0
Width [All] p0: scope1count=1 scope1_0_kind=Board scope1_0_value=Board scope2count=1 scope2_0_kind=Board scope2_0_value=Board commentlength=0 maxlimit=50 minlimit=5 preferedwidth=6
Width [All] p1: maxlimit=50 minlimit=5 preferedwidth=6 minimp=50.000000 maximp=50.000000 favimp=50.000000 checkconnectedcopper=TRUE
14 further rules are at their usual default settings.

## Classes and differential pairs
component class MCU009B_Xds100v2Emu: C1:A C2:A C3:A C4:A C5:A C6:A C7:A C8:A C9:A C10:A C11:A C12:A C13:A C14:A C15:A C16:A C17:A C18:A D1:A D2:A D3:A D4:A J1:A L1:A L2:A R1:A R2:A R3:A R4:A R5:A R6:A R7:A R8:A R9:A R10:A R11:A R12:A R13:A R14:A TP1:A TP2:A TP3:A U1:A U2:A U3:A U4:A Y1:A
component class MCU009B_Power+Misc: C1 C2 C3 C4 C5 C6 C7 C8 C9 C10 C11 C12 C13 C14 C15 C16 C17 C18 C19 C20 C21 C22 C23 C24 C25 C26 C27 C28 C29 C30 C31 D1 D2 D3 L1 L2 L3 R10 R11 R12 R13 R14 R15 R16 R17 R18 R19 R20 R21 R22 R23 R24 R25 R26 R27 R28 R29 R30 R31 R32 R33 R34 S1 TP1 TP2 TP3 TP4 TP5 TP6 U2 U3 U4 Y1
component class MCU009B_EmuInterface: C19:A C20:A C21:A C22:A C23:A C24:A C25:A C26:A R15:A R16:A S1:A U5:A U6:A U7:A U8:A
component class MCU009B_Connector+IO: EC1 J1 R1 R2 R3 R4 R5 R6 R7 R8 R9 S2 S3 S4 S5 S6 U1
component class MCU009B_ADC: C32 C33 C34 C35 C36 C37 C38 C39 C40 C41 C42 C43 C44 C45 C46 C47 C48 C49 C50 C51 C52 C53 C54 C55 C56 C57 C58 C59 C60 C61 R35 R36 R37 R38 R39 R40 R41 R42 R43 R44 R45 R46 R47 R48 R49 R50 R51 R52 R53 R54 R55 R56 R57 R58 R59 R60 R61 R62 R63 R64 S7 S8 U5 U6 U7 U8 U9
component class Header: J1
component class AssemblyNote: ZZ1 ZZ2 ZZ3
component class FiducialMark: FID1 FID2 FID3 FID4 FID5 FID6
component class MCU009B_EVM_Hardware: FID1 FID2 FID3 FID4 FID5 FID6 Logo1 Logo2 Logo3 LOGO4 ZZ1 ZZ2 ZZ3
component class Logo: Logo1

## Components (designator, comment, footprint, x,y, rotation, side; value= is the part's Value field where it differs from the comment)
C1 "GRM188R61A106ME69D" 0603 1400,1370 r0 bottom
C1:A "GRM155R71A104KA01D" 0402 260.2,1514.84 r180 top
C2 "GRM188R61A106ME69D" 0603 1390,1370 r0 top
C2:A "GRM188R60J475ME19D" 0603 485,1495 r180 bottom
C3 "GRM155R71A104KA01D" 0402 1375,1130 r90 bottom
C3:A "GRM188R60J475ME19D" 0603 265.2,1579.84 r0 top
C4 "GRM155R71A104KA01D" 0402 1815,1170 r270 bottom
C4:A "GRM155R71C103KA01D" 0402 535.2,1879.84 r270 top
C5 "GRM155R71A104KA01D" 0402 1510,764 r0 bottom
C5:A "GRM188R60J475ME19D" 0603 -10,1395 r270 top
C6 "GRM155R71A104KA01D" 0402 1070,1145 r90 bottom
C6:A "GRM155R71A104KA01D" 0402 310.2,1444.84 r180 top
C7 "GRM21BR61A106KE19L" 0805_HV 1683.1,497.4 r90 bottom
C7:A "GRM155R71A104KA01D" 0402 -15,1045 r90 top
C8 "GRM188R61A106ME69D" 0603 1583.1,512.4 r270 bottom
C8:A "GRM155R71A104KA01D" 0402 340,1090 r180 top
C9 "GRM155R71A104KA01D" 0402 2063.1,1592.4 r270 top
C9:A "GRM155R71A104KA01D" 0402 428.7,1278.74 r90 top
C10 "GRM188R61A225KE34D" 0603 920,1130 r0 bottom
C10:A "GRM155R71A104KA01D" 0402 -19.8,1169.84 r90 top
C11 "GRM188R61A225KE34D" 0603 905,1050 r0 bottom
C11:A "GRM155R71A104KA01D" 0402 435.2,1109.84 r270 top
C12 "GRM188R61A225KE34D" 0603 1210,930 r180 bottom
C12:A "GRM155R71A104KA01D" 0402 200.35,991.34 r180 top
C13 "GRM188R61A225KE34D" 0603 1315,780 r270 bottom
C13:A "GRM188R60J475ME19D" 0603 470.54,1712.65 r90 bottom
C14 "GRM155R71A104KA01D" 0402 1225,1092 r0 bottom
C14:A "GRM155R71A104KA01D" 0402 -145,1305 r180 bottom
C15 "GRM155R71A104KA01D" 0402 1540.9,649.99 r180 bottom
C15:A "GRM188R60J475ME19D" 0603 85.2,1614.84 r180 bottom
C16 "GRM155R71A104KA01D" 0402 1650,1120 r90 bottom
C16:A "GRM155R71A104KA01D" 0402 105.2,1549.84 r0 bottom
C17 "GRM155R71A104KA01D" 0402 1385,1230 r0 bottom
C17:A "GRM1555C1H270JA01D" 0402 -204.8,1344.84 r90 top
C18 "GRM155R71A104KA01D" 0402 1520,1280 r180 bottom
C18:A "GRM1555C1H270JA01D" 0402 -50,1545 r270 bottom
C19 "GRM188R61A225KE34D" 0603 1540,1540 r0 bottom
C19:A "GRM155R71A104KA01D" 0402 621.88,1873.36 r90 bottom
C20 "GRM188R61A106ME69D" 0603 1541.5,1375 r0 bottom
C20:A "GRM155R71A104KA01D" 0402 980,1875 r270 bottom
C21 "GRM188R61A106ME69D" 0603 1540,1445 r0 bottom
C21:A "GRM155R71A104KA01D" 0402 655.99,1612.64 r90 bottom
C22 "GRM1555C1H150JA01D" 0402 1995,1045 r90 bottom
C22:A "GRM155R71A104KA01D" 0402 895,1608.62 r270 bottom
C23 "GRM1555C1H150JA01D" 0402 1845,1360 r0 bottom
C23:A "GRM155R71A104KA01D" 0402 646.99,1239.64 r270 bottom
C24 "GRM188R61A106ME69D" 0603 2225,860 r90 bottom
C24:A "GRM155R71A104KA01D" 0402 896.22,1245.87 r90 bottom
C25 "GRM155R71A104KA01D" 0402 2080,825 r0 bottom
C25:A "GRM155R71A104KA01D" 0402 1670,1841 r90 bottom
C26 "GRM155R71C103KA01D" 0402 2135,1030 r270 top
C26:A "1812SC103KAT1A" 1812 776.22,1860.87 r180 bottom
C27 "GRM188R61A106ME69D" 0603 2065,1050 r270 top
C28 "GRM155R71C102KA01D" 0402 1618.1,1492.4 r180 top
C29 "GRM155R71C103KA01D" 0402 2185,1375 r180 bottom
C30 "GRM155R71C103KA01D" 0402 2185,1180 r0 top
C31 "GRM155R71A104KA01D" 0402 2173.1,1262.4 r0 bottom
C32 "GRM155R71A104KA01D" 0402 150,495 r270 top
C33 "GRM155R71A104KA01D" 0402 400,480 r270 top
C34 "GRM1885C1H331JA01D" 0603 538.1,534 r90 bottom
C35 "GRM1885C1H331JA01D" 0603 600,695 r270 bottom
C36 "GRM1885C1H331JA01D" 0603 638.1,534 r90 bottom
C37 "GRM1885C1H331JA01D" 0603 700,695 r270 bottom
C38 "GRM1885C1H331JA01D" 0603 740,534 r90 bottom
C39 "GRM1885C1H331JA01D" 0603 800,695 r270 bottom
C40 "GRM1885C1H331JA01D" 0603 840,534 r90 bottom
C41 "GRM188R71C104KA01D" 0603 -136.9,652.4 r90 bottom
C42 "GRM188R71C104KA01D" 0603 85,653.51 r90 bottom
C43 "GRM188R71C104KA01D" 0603 88.1,337.4 r270 bottom
C44 "GRM188R71C104KA01D" 0603 -141.9,337.4 r270 bottom
C45 "GRM188R71C104KA01D" 0603 818.1,137.4 r0 bottom
C46 "GRM188R71C104KA01D" 0603 353.1,132.4 r0 bottom
C47 "GRM188R71C104KA01D" 0603 353.1,207.4 r0 bottom
C48 "GRM188R71C104KA01D" 0603 -141.9,337.4 r90 top
C49 "GRM188R71C104KA01D" 0603 88.1,337.4 r90 top
C50 "GRM188R71C104KA01D" 0603 85,653.5 r270 top
C51 "GRM188R71C104KA01D" 0603 -136.9,652.4 r270 top
C52 "GRM188R71C104KA01D" 0603 388.1,337.4 r90 bottom
C53 "GRM188R71C104KA01D" 0603 163.1,337.4 r90 bottom
C54 "GRM188R71C104KA01D" 0603 163.1,652.4 r270 bottom
C55 "GRM188R71C104KA01D" 0603 388.1,652.4 r270 bottom
C56 "GRM188R71C104KA01D" 0603 163.1,337.4 r90 top
C57 "GRM188R71C104KA01D" 0603 388.1,337.4 r90 top
C58 "GRM188R71C104KA01D" 0603 388.1,652.4 r270 top
C59 "GRM188R71C104KA01D" 0603 163.1,652.4 r270 top
C60 "GRM188R61A225KE34D" 0603 1115,700 r180 bottom
C61 "GRM188R61A225KE34D" 0603 1115,765 r180 bottom
D1 "150080VS75000" WL-SMCW_Green_0805 2223.1,947.4 r270 top
D1:A "MBRM110ET1G" POWERMITE 230.2,1749.84 r90 top
D2 "150080SS75000" WL-SMCW_RED_0805 2116.22,1800.87 r90 top
D2:A "150080VS75000" WL-SMCW_Green_0805 405.58,1893.56 r180 top
D3 "150080SS75000" WL-SMCW_RED_0805 2215.91,1800.87 r90 top
D3:A "150080BS75000" WL-SMCW_Blue_0805 -209.8,1083.46 r90 top
D4:A "150080BS75000" WL-SMCW_Blue_0805 -113.01,1083.64 r90 top
EC1 "controlCARD-120HSEC_Edge" controlCARD-120HSEC_Edge 975.2,-245.16 r0 top
FID1 "Fiducial" Fiducial10-20 -12,122 r90 top
FID2 "Fiducial" Fiducial10-20 645,860 r0 top
FID3 "Fiducial" Fiducial10-20 1058.1,1902.4 r0 top
FID4 "Fiducial" Fiducial10-20 -25,120 r90 bottom
FID5 "Fiducial" Fiducial10-20 2110,105 r90 bottom
FID6 "Fiducial" Fiducial10-20 -206.9,1912.4 r90 bottom
J1 "TMM-104-01-T-D" Samtec_TMM-104-01-x-D 2212.99,616.64 r0 top
J1:A "65100516121" Wurth_65100516121 -284.78,1710.87 r270 top
L1 "BLM21PG221SN1D" 0805_HV 1635,525 r180 top
L1:A "HZ0805E601R-10" 0805_HV 347.57,1720.29 r90 bottom
L2 "BKP2125HS600-T" 0805_HV 925,1084 r270 top
L2:A "HZ0805E601R-10" 0805_HV 35.2,1694.84 r180 bottom
L3 "LQM2HPN2R2MG0L" 1008 1390,1465 r180 top
Logo1 "Texas Instruments" TI_Symbol_Overlay_Small 1810,274 r180 bottom
Logo2 "WEEE logo" WEEE_Minimum 2247,349 r90 bottom
Logo3 "FCC disclaimer" FCC_disclaimer 2329,1108 r90 bottom
LOGO4 "CE Mark" CE_Mark_5mm 1388,281 r180 bottom
R1 "CRCW04024K70JNED" 0402 75,170 r270 top
R1:A "CRCW0402680RJNED" 0402 381.47,1892.91 r180 bottom
R2 "CRCW04024K70JNED" 0402 70.2,171.65 r90 bottom
R2:A "CRCW040210K0JNED" 0402 580.99,1535.64 r180 top
R3 "CRCW06030000Z0EA" 0603 2065,735 r0 bottom
R3:A "CRCW04020000Z0ED" 0402 370,1560 r90 bottom
R4 "CRCW06030000Z0EA" 0603 2065,655 r0 bottom
R4:A "CRCW040210K0JNED" 0402 545,1145 r0 bottom
R5 "CRCW06030000Z0EA" 0603 2065,575 r0 bottom
R5:A "CRCW04021K00JNED" 0402 545.2,1064.84 r0 bottom
R6 "CRCW06030000Z0EA" 0603 2065,500 r0 bottom
R6:A "CRCW04020000Z0ED" 0402 -144.8,1689.84 r0 bottom
R7 "CRCW06030000Z0EA" 0603 1865,1080 r180 bottom
R7:A "CRCW04021K00JNED" 0402 -209.8,1059.84 r270 bottom
R8 "CRCW040210K0JNED" 0402 1005,185 r180 bottom
R8:A "CRCW04021K00JNED" 0402 -109.8,1054.84 r270 bottom
R9 "CRCW040210K0JNED" 0402 1180,185 r0 bottom
R9:A "CRCW040210K0JNED" 0402 120,1085 r90 top
R10 "CRCW0402680RJNED" 0402 2116.34,1824.48 r90 bottom
R10:A "CRCW04022K20JNED" 0402 44.99,1178.64 r90 top
R11 "CRCW0402680RJNED" 0402 2215.08,1824.99 r90 bottom
R11:A "CRCW04021K00JNED" 0402 320,1555 r270 bottom
R12 "CRCW040210M0JNED" 0402 2125,1576.38 r90 bottom
R12:A "CRCW04020000Z0ED" 0402 -95,1345 r270 top
R13 "CRCW040210M0JNED" 0402 2210,1571.38 r90 bottom
R13:A "CRCW04020000Z0ED" 0402 330.2,989.84 r180 top
R14 "CRCW08050000Z0EA" 0805_HV 1655,1490 r270 bottom
R14:A "CRCW040212K0JNED" 0402 105.2,1499.84 r0 bottom
R15 "CRCW08050000Z0EA" 0805_HV 1420,1495 r270 bottom
R15:A "CRCW040210K0JNED" 0402 1223.1,1725.4 r90 bottom
R16 "CRCW06030000Z0EA" 0603 1865,1010 r180 bottom
R16:A "CRCW040210K0JNED" 0402 1278.1,1725.4 r90 bottom
R17 "CRCW06030000Z0EA" 0603 1855,1290 r180 bottom
R18 "CRCW06030000Z0EA" 0603 1628.1,1372.4 r0 top
R19 "CRCW06030000Z0EA" 0603 1255,1435 r180 bottom
R20 "CRCW08050000Z0EA" 0805_HV 1970,890 r270 top
R21 "CRCW06030000Z0EA" 0603 1525,1405 r270 top
R22 "CRCW06030000Z0EA" 0603 1288.1,1402.4 r90 top
R23 "CRCW0402680RJNED" 0402 2092,930 r0 bottom
R24 "CRCW04021R00FKED" 0402 1618.1,1437.4 r180 top
R25 "CRCW040256K0JNED" 0402 1843.1,1799.4 r90 bottom
R26 "CRCW040256K0JNED" 0402 1898.1,1799.4 r270 bottom
R27 "CRCW04022K20JNED" 0402 2188.1,1447.4 r0 bottom
R28 "CRCW06030000Z0EA" 0603 1893.1,1322.4 r90 top
R29 "CRCW04020000Z0ED" 0402 2188.1,1447.4 r180 top
R30 "CRCW04022K20JNED" 0402 2185,1180 r180 bottom
R31 "CRCW04022K20JNED" 0402 1848.1,922.4 r0 top
R32 "CRCW06030000Z0EA" 0603 1818.1,1322.4 r90 top
R33 "CRCW04022K20JNED" 0402 1845,1621.38 r90 bottom
R34 "CRCW04022K20JNED" 0402 1900,1621.38 r270 bottom
R35 "CRCW06030000Z0EA" 0603 745,358 r0 bottom
R36 "CRCW06030000Z0EA" 0603 -66.9,337.4 r90 top
R37 "CRCW06030000Z0EA" 0603 -61.9,652.4 r90 bottom
R38 "CRCW06030000Z0EA" 0603 13.1,337.4 r90 top
R39 "CRCW06030000Z0EA" 0603 13.1,652.4 r90 bottom
R40 "CRCW06030000Z0EA" 0603 13.1,337.4 r270 bottom
R41 "CRCW06030000Z0EA" 0603 13.1,652.4 r270 top
R42 "CRCW06030000Z0EA" 0603 -66.9,337.4 r270 bottom
R43 "CRCW06030000Z0EA" 0603 818.1,212.4 r0 bottom
R44 "CRCW06030000Z0EA" 0603 -61.9,652.4 r270 top
R45 "CRCW06030000Z0EA" 0603 488.1,132.4 r180 bottom
R46 "CRCW06030000Z0EA" 0603 488.1,207.4 r180 bottom
R47 "CRCW06030000Z0EA" 0603 313.1,337.4 r90 bottom
R48 "CRCW06030000Z0EA" 0603 911.1,892.4 r0 top
R49 "CRCW06030000Z0EA" 0603 238.1,337.4 r90 bottom
R50 "CRCW06030000Z0EA" 0603 911.1,817.4 r0 top
R51 "CRCW06030000Z0EA" 0603 912.1,967.4 r0 top
R52 "CRCW06030000Z0EA" 0603 1265,495 r90 top
R53 "CRCW06030000Z0EA" 0603 238.1,652.4 r270 bottom
R54 "CRCW06030000Z0EA" 0603 1433.1,507.4 r90 top
R55 "CRCW06030000Z0EA" 0603 911.1,892.4 r0 bottom
R56 "CRCW06030000Z0EA" 0603 911.1,817.4 r0 bottom
R57 "CRCW06030000Z0EA" 0603 912.1,967.4 r0 bottom
R58 "CRCW06030000Z0EA" 0603 1175,505 r90 top
R59 "CRCW06030000Z0EA" 0603 1358.1,507.4 r90 top
R60 "CRCW06030000Z0EA" 0603 313.1,652.4 r270 bottom
R61 "CRCW06030000Z0EA" 0603 238.1,337.4 r90 top
R62 "CRCW06030000Z0EA" 0603 313.1,337.4 r90 top
R63 "CRCW06030000Z0EA" 0603 313.1,652.4 r270 top
R64 "CRCW06030000Z0EA" 0603 238.1,652.4 r270 top
S1 "218-2LPST" SW_218-2LP 1868.1,1762.4 r270 top
S1:A "218-2LPST" SW_218-2LP 1248.1,1762.4 r90 top
S2 "CAS-220TA" SW_CAS-220TA 1398.1,252.4 r0 top
S3 "CAS-220TA" SW_CAS-220TA 1675,252.4 r180 top
S4 "CAS-220TA" SW_CAS-220TA 1093.1,252.4 r0 top
S5 "CAS-D20TA" SW_CAS-D20TA 1868.1,602.4 r180 top
S6 "CAS-D20TA" SW_CAS-D20TA 1950,252.4 r0 top
S7 "218-8LPST" SW_218-8LP 713.1,512.4 r90 top
S8 "218-2LPST" SW_218-2LP 668.1,202.4 r0 top
TP1 "TESTPOINT" TP_50MIL-25MILHOLE -96.9,762.4 r0 top
TP1:A "TESTPOINT" TP_50MIL-25MILHOLE -93.8,948.84 r90 top
TP2 "TESTPOINT" TP_50MIL-25MILHOLE 1863.1,832.4 r0 top
TP2:A "TESTPOINT" TP_50MIL-25MILHOLE -193.8,948.84 r90 top
TP3 "TESTPOINT" TP_50MIL-25MILHOLE 1180,1365 r0 top
TP3:A "TESTPOINT" TP_50MIL-25MILHOLE 13.1,947.4 r90 top
TP4 "TESTPOINT" TP_50MIL-25MILHOLE 13.1,762.4 r0 top
TP5 "TESTPOINT" TP_50MIL-25MILHOLE 2053.1,1447.4 r0 top
TP6 "TESTPOINT" TP_50MIL-25MILHOLE 2225,1095 r270 top
U1 "F280049CPZS" PZ0100A_N 1378.1,964.56 r0 top
U1:A "TPS73033DBVR" DBV0005A_N 405.2,1709.84 r90 top
U2 "SN74LVC2G07DBVR" DBV0006A_N 2165.91,1600.87 r90 top
U2:A "FT2232HL-REEL" LQFP64_N 226.22,1210.87 r270 bottom
U3 "TPS73633DBVR" DBV0005A_N 2095,880 r90 top
U3:A "TPD2E001DRLR" DRL0005A 185.2,1704.84 r180 bottom
U4 "TPS3702CX33DDCR" DDC0006A_N 2173.1,1317.4 r270 top
U4:A "93LC56C-I/SN" SOIC-8 225.2,1229.84 r0 top
U5 "TPD4E001QDBVRQ1" DBV0006A_N -26.9,492.4 r90 top
U5:A "ISO7220CD" D0008B_N 776.22,1810.87 r0 top
U6 "TPD4E001QDBVRQ1" DBV0006A_N -26.9,492.4 r270 bottom
U6:A "ISO7220CD" D0008B_N 776.22,1560.87 r0 top
U7 "TPD4E001QDBVRQ1" DBV0006A_N 273.1,492.4 r90 bottom
U7:A "ISO7220CD" D0008B_N 776.22,1290.87 r180 top
U8 "TPD4E001QDBVRQ1" DBV0006A_N 648.1,170.4 r180 bottom
U8:A "SN74ALVC244PWR" PW0020A_N 1546.2,1758.84 r0 top
U9 "TPD4E001QDBVRQ1" DBV0006A_N 273.1,492.4 r90 top
Y1 "20MHz" ECS_ECX-53B 1865.83,1100.67 r180 top
Y1:A "12MHz" ECS_ECX-53B -159.8,1449.84 r0 bottom
ZZ1 "These assemblies are ESD sensitive, ESD precautions shall be observed." AssemblyNote -4235.9,5731.96 r0 top
ZZ2 "These assemblies must be clean and free from flux and all contaminants. Use of no clean flux is not acceptable." AssemblyNote -4235.9,5643.4 r0 top
ZZ3 "These assemblies must comply with workmanship standards IPC-A-610 Class 2, unless otherwise specified." AssemblyNote -4234.6,5555.9 r0 top

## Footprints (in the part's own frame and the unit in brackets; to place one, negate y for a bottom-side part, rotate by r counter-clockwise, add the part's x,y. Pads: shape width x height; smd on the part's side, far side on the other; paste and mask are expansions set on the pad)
0402 [mm] "0402 from SM-752 data"
  rect 0.8x0.6 smd: 1(-0.6,0) 2(0.6,0)
  silkscreen extent -1.22,-0.52 1.22,0.52
0603 [mm] "0603 from SM-752 data"
  rect 1x0.95 smd: 1(-0.8,0) 2(0.8,0)
  silkscreen extent -1.52,-0.69 1.52,0.69
0805_HV [mil] "0805 with 30mil clearance between pads"
  rect 50x63 smd: 1(-40,0) 2(40,0)
  silkscreen extent -74,-40 74,40
1008 [mm] "SMD, Body 2.5x2mm, Height 1.2mm"
  rect 0.8x2.2 smd: 1(-1,0) 2(1,0)
  silkscreen extent -0.4,-1.2 0.4,1.2
1812 [mm]
  rect 1.6x3.4 smd: 1(-2,0) 2(2,0)
  silkscreen extent -0.8,-1.6 0.8,1.6
AssemblyNote [mil] "Assembly Note"
CE_Mark_5mm [mil] "Minimum text height for CE Mark"
controlCARD-120HSEC_Edge [mm] "Edge Connector, 0.8mm, 60x2, pad numbers do not match Samtec datasheet"
  rect 0.55x2.8 smd paste-2.5 mask+0: 1(-23.6,2.4) 3(-22.8,2.4) 5(-22,2.4) 7(-21.2,2.4) 9(-20.4,2.4) 11(-19.6,2.4) 13(-18.8,2.4) 15(-18,2.4) 17(-17.2,2.4) 19(-16.4,2.4) 21(-15.6,2.4) 23(-14.8,2.4) 25(-14,2.4) 27(-13.2,2.4) 29(-12.4,2.4) 31(-11.6,2.4) 33(-10.8,2.4) 35(-10,2.4) 37(-9.2,2.4) 39(-8.4,2.4) 41(-7.6,2.4) 43(-6.8,2.4) 45(-6,2.4) 47(-5.2,2.4) 49(-4.4,2.4) 51(-3.6,2.4) 53(-2.8,2.4) 55(-2,2.4) 57(2,2.4) 59(2.8,2.4) 61(3.6,2.4) 63(4.4,2.4) 65(5.2,2.4) 67(6,2.4) 69(6.8,2.4) 71(7.6,2.4) 73(8.4,2.4) 75(9.2,2.4) 77(10,2.4) 79(10.8,2.4) 81(11.6,2.4) 83(12.4,2.4) 85(13.2,2.4) 87(14,2.4) 89(14.8,2.4) 91(15.6,2.4) 93(16.4,2.4) 95(17.2,2.4) 97(18,2.4) 99(18.8,2.4) 101(19.6,2.4) 103(20.4,2.4) 105(21.2,2.4) 107(22,2.4) 109(22.8,2.4) 111(23.6,2.4) 113(24.4,2.4) 115(25.2,2.4) 117(26,2.4) 119(26.8,2.4)
  rect 0.55x2.8 smd far side paste-2.5 mask+0: 2(-23.6,2.4) 4(-22.8,2.4) 6(-22,2.4) 8(-21.2,2.4) 10(-20.4,2.4) 12(-19.6,2.4) 14(-18.8,2.4) 16(-18,2.4) 18(-17.2,2.4) 20(-16.4,2.4) 22(-15.6,2.4) 24(-14.8,2.4) 26(-14,2.4) 28(-13.2,2.4) 30(-12.4,2.4) 32(-11.6,2.4) 34(-10.8,2.4) 36(-10,2.4) 38(-9.2,2.4) 40(-8.4,2.4) 42(-7.6,2.4) 44(-6.8,2.4) 46(-6,2.4) 48(-5.2,2.4) 50(-4.4,2.4) 52(-3.6,2.4) 54(-2.8,2.4) 56(-2,2.4) 58(2,2.4) 60(2.8,2.4) 62(3.6,2.4) 64(4.4,2.4) 66(5.2,2.4) 68(6,2.4) 70(6.8,2.4) 72(7.6,2.4) 74(8.4,2.4) 76(9.2,2.4) 78(10,2.4) 80(10.8,2.4) 82(11.6,2.4) 84(12.4,2.4) 86(13.2,2.4) 88(14,2.4) 90(14.8,2.4) 92(15.6,2.4) 94(16.4,2.4) 96(17.2,2.4) 98(18,2.4) 100(18.8,2.4) 102(19.6,2.4) 104(20.4,2.4) 106(21.2,2.4) 108(22,2.4) 110(22.8,2.4) 112(23.6,2.4) 114(24.4,2.4) 116(25.2,2.4) 118(26,2.4) 120(26.8,2.4)
D0008B_N [mil] "SOIC, 8-Leads, Body 4.9x3.9mm, Pitch 1.27mm, IPC Medium Density"
  oval 55x23.62 smd: 1(-108.5,75) 2(-108.5,25) 3(-108.5,-25) 4(-108.5,-75) 5(108.5,-75) 6(108.5,-25) 7(108.5,25) 8(108.5,75)
  silkscreen extent -130,-98 35,98
DBV0005A_N [mm] "SOT23, 5-Leads, Body 2.9x1.6mm, Pitch 0.95mm, Lead Span 2.8mm, IPC Medium Density"
  rrect17% 1x0.6 smd: 1(-1.375,0.95) 2(-1.375,0) 3(-1.375,-0.95) 4(1.375,-0.95) 5(1.375,0.95)
  silkscreen extent -0.25,-1.55 0.25,1.55
DBV0006A_N [mm] "SOT23, 6-Leads, Body 2.9x1.6mm, Pitch 0.95mm, Lead Span 2.8mm, IPC Medium Density"
  rrect17% 1x0.6 smd: 1(-1.375,0.95) 2(-1.375,0) 3(-1.375,-0.95) 4(1.375,-0.95) 5(1.375,0) 6(1.375,0.95)
  silkscreen extent -1.68,-1.55 0.5,1.55
DDC0006A_N [mm]
  rrect17% 1x0.6 smd: 1(-1.375,0.95) 2(-1.375,0) 3(-1.375,-0.95) 4(1.375,-0.95) 5(1.375,0) 6(1.375,0.95)
  silkscreen extent -1.75,-1.52 0.7,1.53
DRL0005A [mm] "SOTFL, 5-Flat Leads, Body 1.2x1.6x0.6mm, Pitch 0.5mm, TI recommended"
  rrect33% 0.67x0.3 smd: 1(-0.74,0.5) 2(-0.74,0) 3(-0.74,-0.5) 4(0.74,-0.5) 5(0.74,0.5)
  silkscreen extent -0.9,-0.95 0.5,0.95
ECS_ECX-53B [mm] "SMD, 4-Leads, Body 5x3.2mm"
  rect 1.25x1.6 smd: 1(-1.1,1.85) 2(-1.1,-1.85) 3(1.1,-1.85) 4(1.1,1.85)
  silkscreen extent -2.05,-2.7 1.83,2.73
FCC_disclaimer [mil]
Fiducial10-20 [mm]
  round 1 smd mask+0: 1(0,0)
  Top Layer keep-out circle w1.178: c0,0 r0.5
LQFP64_N [mm] "Thin QFP, 64-Leads, Body 10x10mm, Pitch 0.5mm, IPC Medium Density"
  oval 1.8x0.3 smd: 1(-5.55,3.75) 2(-5.55,3.25) 3(-5.55,2.75) 4(-5.55,2.25) 5(-5.55,1.75) 6(-5.55,1.25) 7(-5.55,0.75) 8(-5.55,0.25) 9(-5.55,-0.25) 10(-5.55,-0.75) 11(-5.55,-1.25) 12(-5.55,-1.75) 13(-5.55,-2.25) 14(-5.55,-2.75) 15(-5.55,-3.25) 16(-5.55,-3.75) 33(5.55,-3.75) 34(5.55,-3.25) 35(5.55,-2.75) 36(5.55,-2.25) 37(5.55,-1.75) 38(5.55,-1.25) 39(5.55,-0.75) 40(5.55,-0.25) 41(5.55,0.25) 42(5.55,0.75) 43(5.55,1.25) 44(5.55,1.75) 45(5.55,2.25) 46(5.55,2.75) 47(5.55,3.25) 48(5.55,3.75)
  oval 0.3x1.8 smd: 17(-3.75,-5.55) 18(-3.25,-5.55) 19(-2.75,-5.55) 20(-2.25,-5.55) 21(-1.75,-5.55) 22(-1.25,-5.55) 23(-0.75,-5.55) 24(-0.25,-5.55) 25(0.25,-5.55) 26(0.75,-5.55) 27(1.25,-5.55) 28(1.75,-5.55) 29(2.25,-5.55) 30(2.75,-5.55) 31(3.25,-5.55) 32(3.75,-5.55) 49(3.75,5.55) 50(3.25,5.55) 51(2.75,5.55) 52(2.25,5.55) 53(1.75,5.55) 54(1.25,5.55) 55(0.75,5.55) 56(0.25,5.55) 57(-0.25,5.55) 58(-0.75,5.55) 59(-1.25,5.55) 60(-1.75,5.55) 61(-2.25,5.55) 62(-2.75,5.55) 63(-3.25,5.55) 64(-3.75,5.55)
  silkscreen extent -5.67,-4.25 4.25,4.57
POWERMITE [mil] "On Semi recommended land pattern, 457-04.pdf Rev 04E dated 2008-11-26"
  rect 105x100 smd: 1(-46,0)
  rect 30x50 smd: 2(46,0)
  silkscreen extent -124,-63 61,63
PW0020A_N [mm] "TSOP, 20-Leads, Body 6.5x4.4mm, Pitch 0.65mm, IPC Medium Density"
  oval 1.4x0.45 smd: 1(-2.95,2.925) 2(-2.95,2.275) 3(-2.95,1.625) 4(-2.95,0.975) 5(-2.95,0.325) 6(-2.95,-0.325) 7(-2.95,-0.975) 8(-2.95,-1.625) 9(-2.95,-2.275) 10(-2.95,-2.925) 11(2.95,-2.925) 12(2.95,-2.275) 13(2.95,-1.625) 14(2.95,-0.975) 15(2.95,-0.325) 16(2.95,0.325) 17(2.95,0.975) 18(2.95,1.625) 19(2.95,2.275) 20(2.95,2.925)
  Top Overlay keep-out lines w0.2: -1.85,-3.3 1.85,-3.3
  silkscreen extent -3.5,-3.3 1.85,3.4
PZ0100A_N [mm] "TSQFP, 100-Leads, Body 16.2x16.2mm (max), Pitch 0.50mm, IPC Medium Density"
  oval 1.45x0.3 smd: 1(-7.725,6) 2(-7.725,5.5) 3(-7.725,5) 4(-7.725,4.5) 5(-7.725,4) 6(-7.725,3.5) 7(-7.725,3) 8(-7.725,2.5) 9(-7.725,2) 10(-7.725,1.5) 11(-7.725,1) 12(-7.725,0.5) 13(-7.725,0) 14(-7.725,-0.5) 15(-7.725,-1) 16(-7.725,-1.5) 17(-7.725,-2) 18(-7.725,-2.5) 19(-7.725,-3) 20(-7.725,-3.5) 21(-7.725,-4) 22(-7.725,-4.5) 23(-7.725,-5) 24(-7.725,-5.5) 25(-7.725,-6) 51(7.725,-6) 52(7.725,-5.5) 53(7.725,-5) 54(7.725,-4.5) 55(7.725,-4) 56(7.725,-3.5) 57(7.725,-3) 58(7.725,-2.5) 59(7.725,-2) 60(7.725,-1.5) 61(7.725,-1) 62(7.725,-0.5) 63(7.725,0) 64(7.725,0.5) 65(7.725,1) 66(7.725,1.5) 67(7.725,2) 68(7.725,2.5) 69(7.725,3) 70(7.725,3.5) 71(7.725,4) 72(7.725,4.5) 73(7.725,5) 74(7.725,5.5) 75(7.725,6)
  oval 0.3x1.45 smd: 26(-6,-7.725) 27(-5.5,-7.725) 28(-5,-7.725) 29(-4.5,-7.725) 30(-4,-7.725) 31(-3.5,-7.725) 32(-3,-7.725) 33(-2.5,-7.725) 34(-2,-7.725) 35(-1.5,-7.725) 36(-1,-7.725) 37(-0.5,-7.725) 38(0,-7.725) 39(0.5,-7.725) 40(1,-7.725) 41(1.5,-7.725) 42(2,-7.725) 43(2.5,-7.725) 44(3,-7.725) 45(3.5,-7.725) 46(4,-7.725) 47(4.5,-7.725) 48(5,-7.725) 49(5.5,-7.725) 50(6,-7.725) 76(6,7.725) 77(5.5,7.725) 78(5,7.725) 79(4.5,7.725) 80(4,7.725) 81(3.5,7.725) 82(3,7.725) 83(2.5,7.725) 84(2,7.725) 85(1.5,7.725) 86(1,7.725) 87(0.5,7.725) 88(0,7.725) 89(-0.5,7.725) 90(-1,7.725) 91(-1.5,7.725) 92(-2,7.725) 93(-2.5,7.725) 94(-3,7.725) 95(-3.5,7.725) 96(-4,7.725) 97(-4.5,7.725) 98(-5,7.725) 99(-5.5,7.725) 100(-6,7.725)
  silkscreen extent -7.7,-6.3 6.3,6.82
Samtec_TMM-104-01-x-D [mm] "Header, 2mm, 4x2, TH"
  rect 1.4x1.4 hole 0.89: 1(-1,3)
  round 1.4 hole 0.89: 2(1,3) 3(-1,1) 4(1,1) 5(-1,-1) 6(1,-1) 7(-1,-3) 8(1,-3)
  silkscreen extent -2.4,-4 1.97,4
SOIC-8 [mm] "duplicate of SO-8.  SOIC, 8-Leads, Body 5.0x4.0mm (max), Pitch 1.27mm, IPC Medium Density"
  rrect17% 1.45x0.6 smd: 1(-2.725,1.905) 2(-2.725,0.635) 3(-2.725,-0.635) 4(-2.725,-1.905) 5(2.725,-1.905) 6(2.725,-0.635) 7(2.725,0.635) 8(2.725,1.905)
  silkscreen extent -3.5,-2.5 0.9,2.5
SW_218-2LP [mm] "SMD, 4-Leads, Body 3.71x5.8mm, Pitch 1.27mm"
  rect 1.27x0.76 smd: 1(-3.81,0.635) 2(-3.81,-0.635) 3(3.81,-0.635) 4(3.81,0.635)
  silkscreen extent -2.9,-1.86 2.9,2.09
SW_218-8LP [mm] "SMD, 16-Leads, Body 11.33x5.8mm, Pitch 1.27mm"
  rect 1.27x0.76 smd: 1(-3.81,4.445) 2(-3.81,3.175) 3(-3.81,1.905) 4(-3.81,0.635) 5(-3.81,-0.635) 6(-3.81,-1.905) 7(-3.81,-3.175) 8(-3.81,-4.445) 9(3.81,-4.445) 10(3.81,-3.175) 11(3.81,-1.905) 12(3.81,-0.635) 13(3.81,0.635) 14(3.81,1.905) 15(3.81,3.175) 16(3.81,4.445)
  silkscreen extent -2.9,-5.67 2.9,5.9
SW_CAS-220TA [mm] "COPAL ELECTRONICS"
  rect 1.6x1 smd: 1(-1.85,1.75) 2(-1.85,0) 3(-1.85,-1.75) 4(1.85,1.75) 5(1.85,0) 6(1.85,-1.75)
  silkscreen extent -2.1,-2.9 2,3.7
SW_CAS-D20TA [mm] "SMD, 6-Leads, Body 5.4x3.9mm, Pitch 1.75mm"
  rect 1.6x1 smd: 1(-1.85,1.75) 2(-1.85,0) 3(-1.85,-1.75) 4(1.85,1.75) 5(1.85,0) 6(1.85,-1.75)
  silkscreen extent -1.95,-2.7 1.95,2.9
TI_Symbol_Overlay_Small [mil]
TP_50MIL-25MILHOLE [mil]
  round 50 hole 25: 1(0,0)
WEEE_Minimum [mil] "WEEElie bin"
  silkscreen extent 22,-71 54,74
WL-SMCW_Blue_0805 [mm] "SMD, 2-Leads, Body 2x1.25mm"
  rect 1.1x1.2 smd: 1(-1.05,0) 2(1.05,0)
  silkscreen extent -2.4,-1.1 1.5,1.1
WL-SMCW_Green_0805 [mm] "SMD, 2-Leads, Body 2x1.25mm"
  rect 1.1x1.2 smd: 1(-1.05,0) 2(1.05,0)
  silkscreen extent -2.4,-1.1 1.5,1.1
WL-SMCW_RED_0805 [mm] "SMD, 2-Leads, Body 1.6x0.8mm"
  rect 1.1x1.2 smd: 1(-1.05,0) 2(1.05,0)
  silkscreen extent -2.4,-1.1 1.5,1.1
Wurth_65100516121 [mm] "Connector, Receptacle, USB Mini B 2.0, 5 Position, SMT"
  rect 0.5x2.5 smd: 1(-1.6,8.5) 2(-0.8,8.5) 3(0,8.5) 4(0.8,8.5) 5(1.6,8.5)
  rect 2x2.5 smd: 6(-4.4,8.5) 7(4.4,8.5) 8(-4.4,3) 9(4.4,3)
  round 0.9 hole 0.9 unplated mask+0: ALIGN1(-2.2,5.9) ALIGN2(2.2,5.9)
  silkscreen extent -3.85,0.15 3.85,9.6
